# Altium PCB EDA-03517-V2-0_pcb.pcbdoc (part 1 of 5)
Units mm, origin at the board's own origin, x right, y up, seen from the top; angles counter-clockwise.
Board outline 220 x 264 mm, 8 copper layers (Top Layer, L2, L3, L4, L5, L6, L7, Bottom Layer), stack 2.18 mm thick; 439 components, 290 nets, 1011 pads, 273 vias.
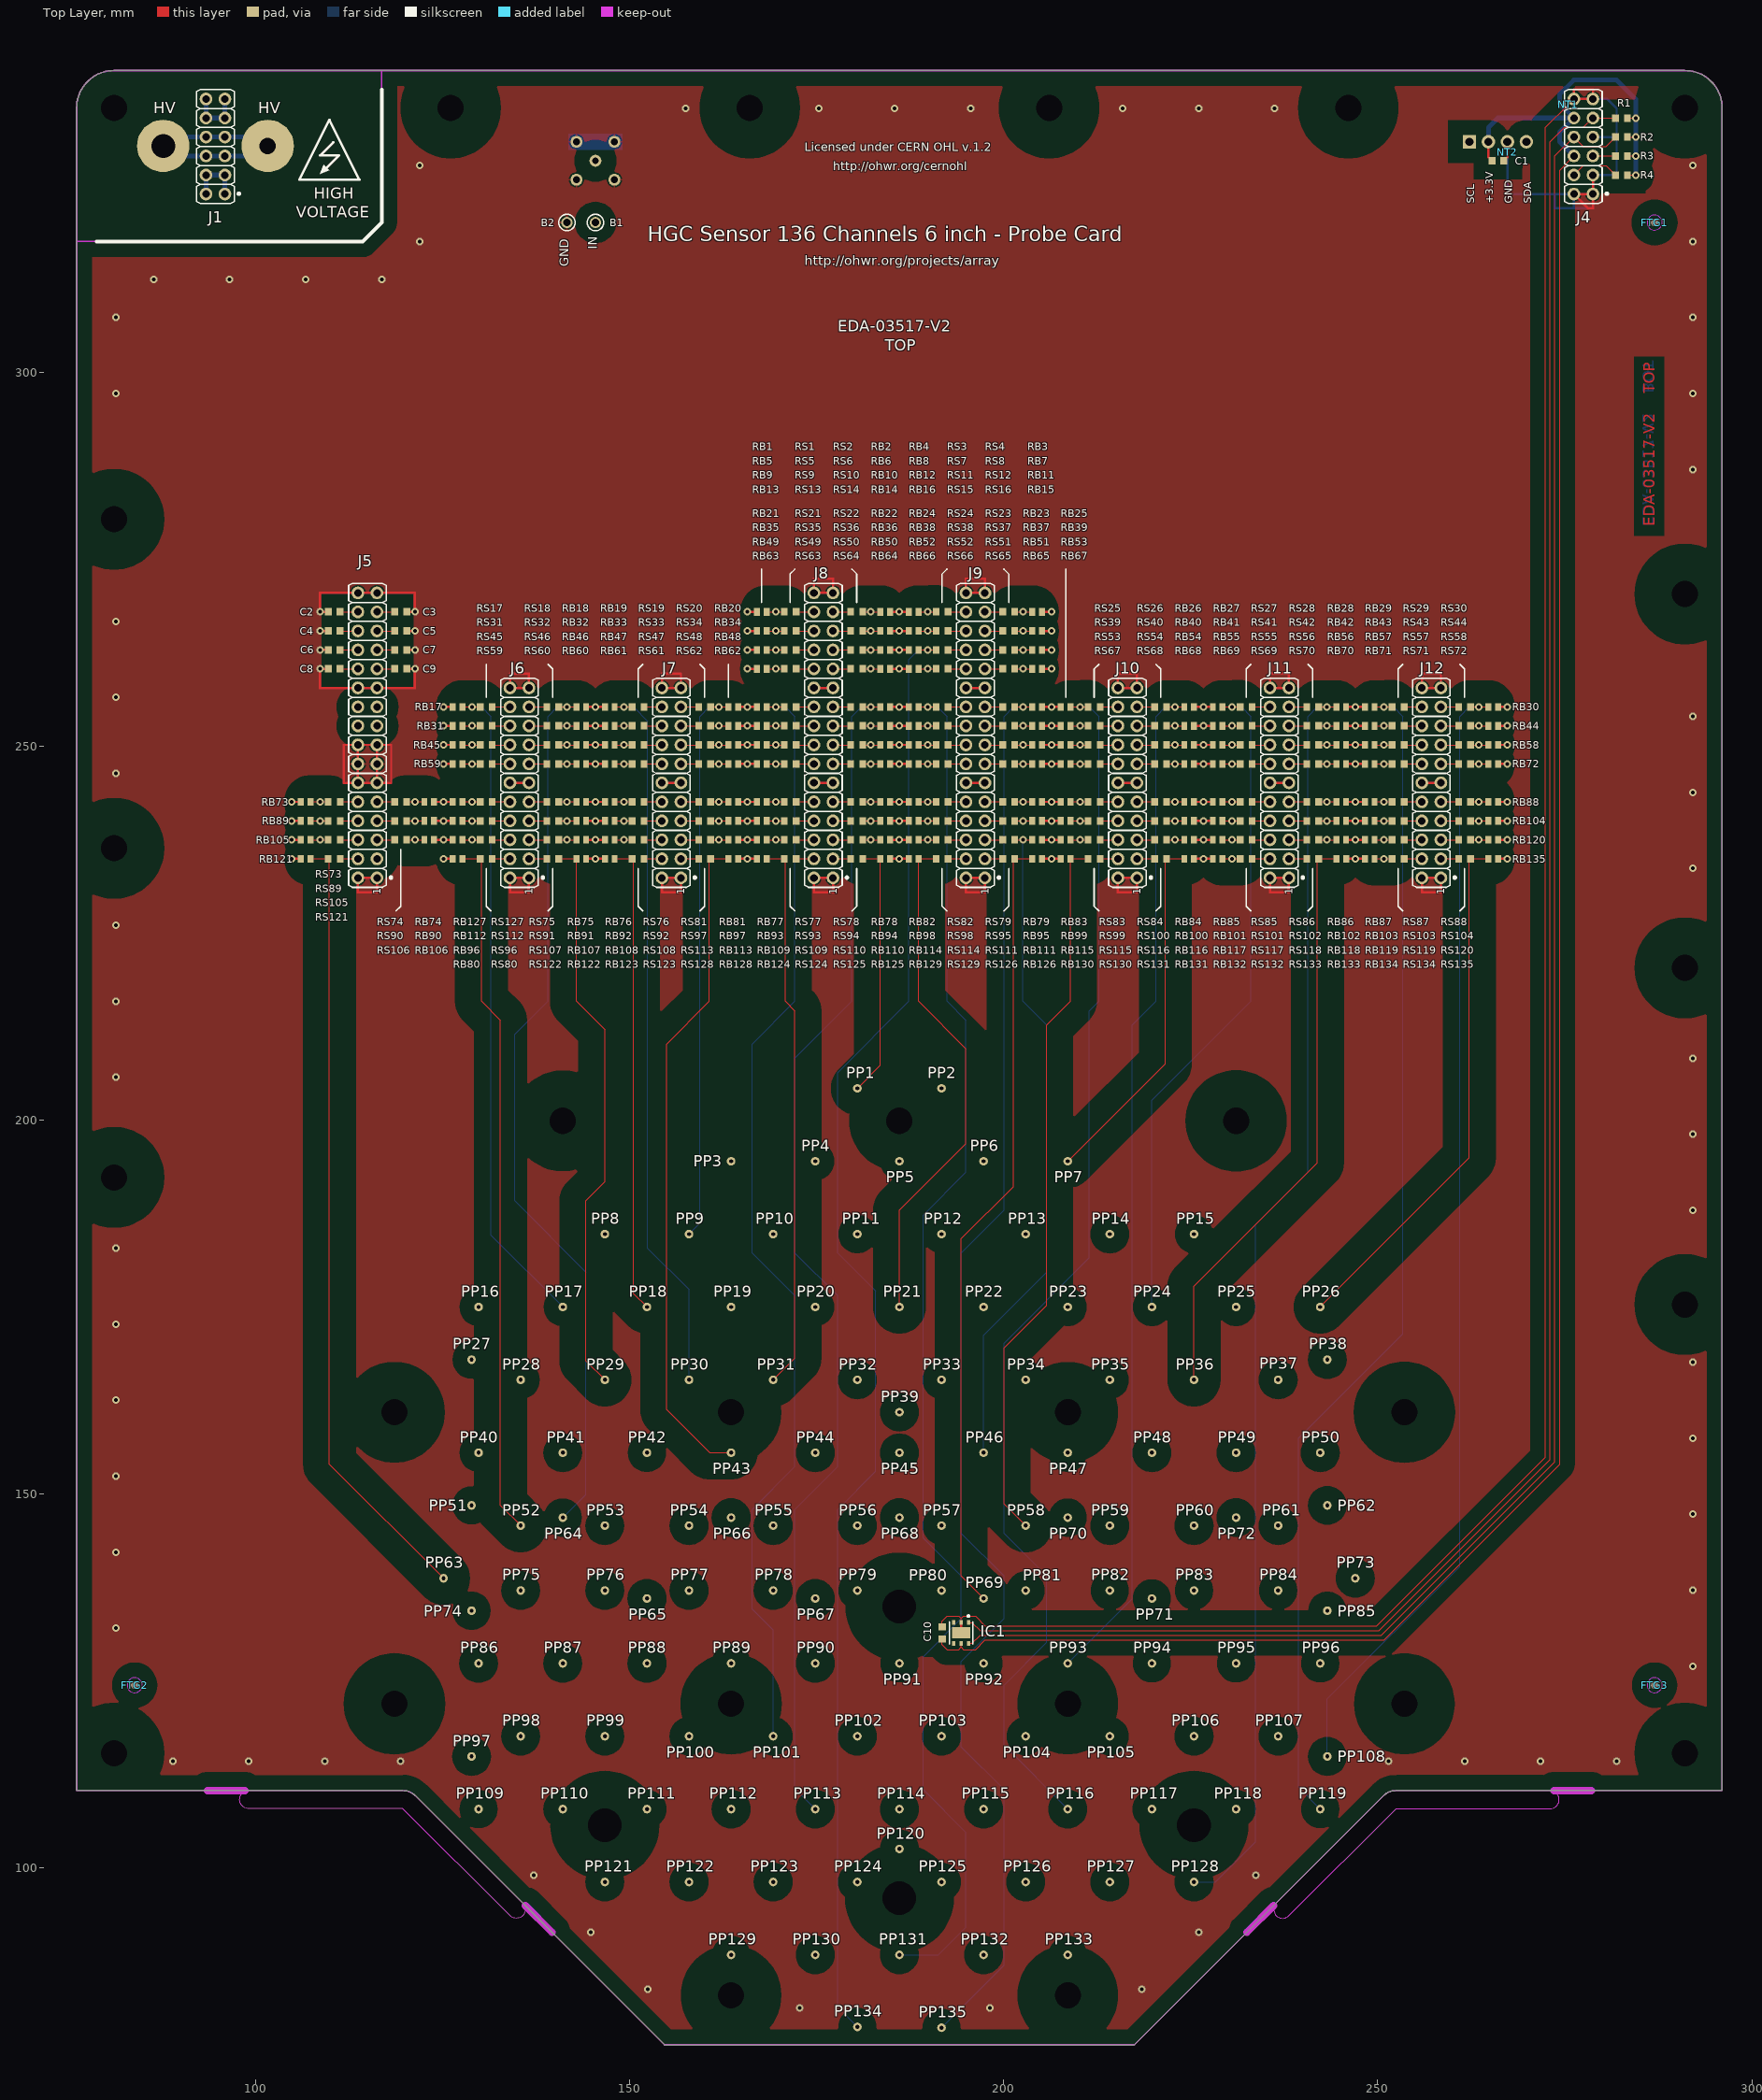
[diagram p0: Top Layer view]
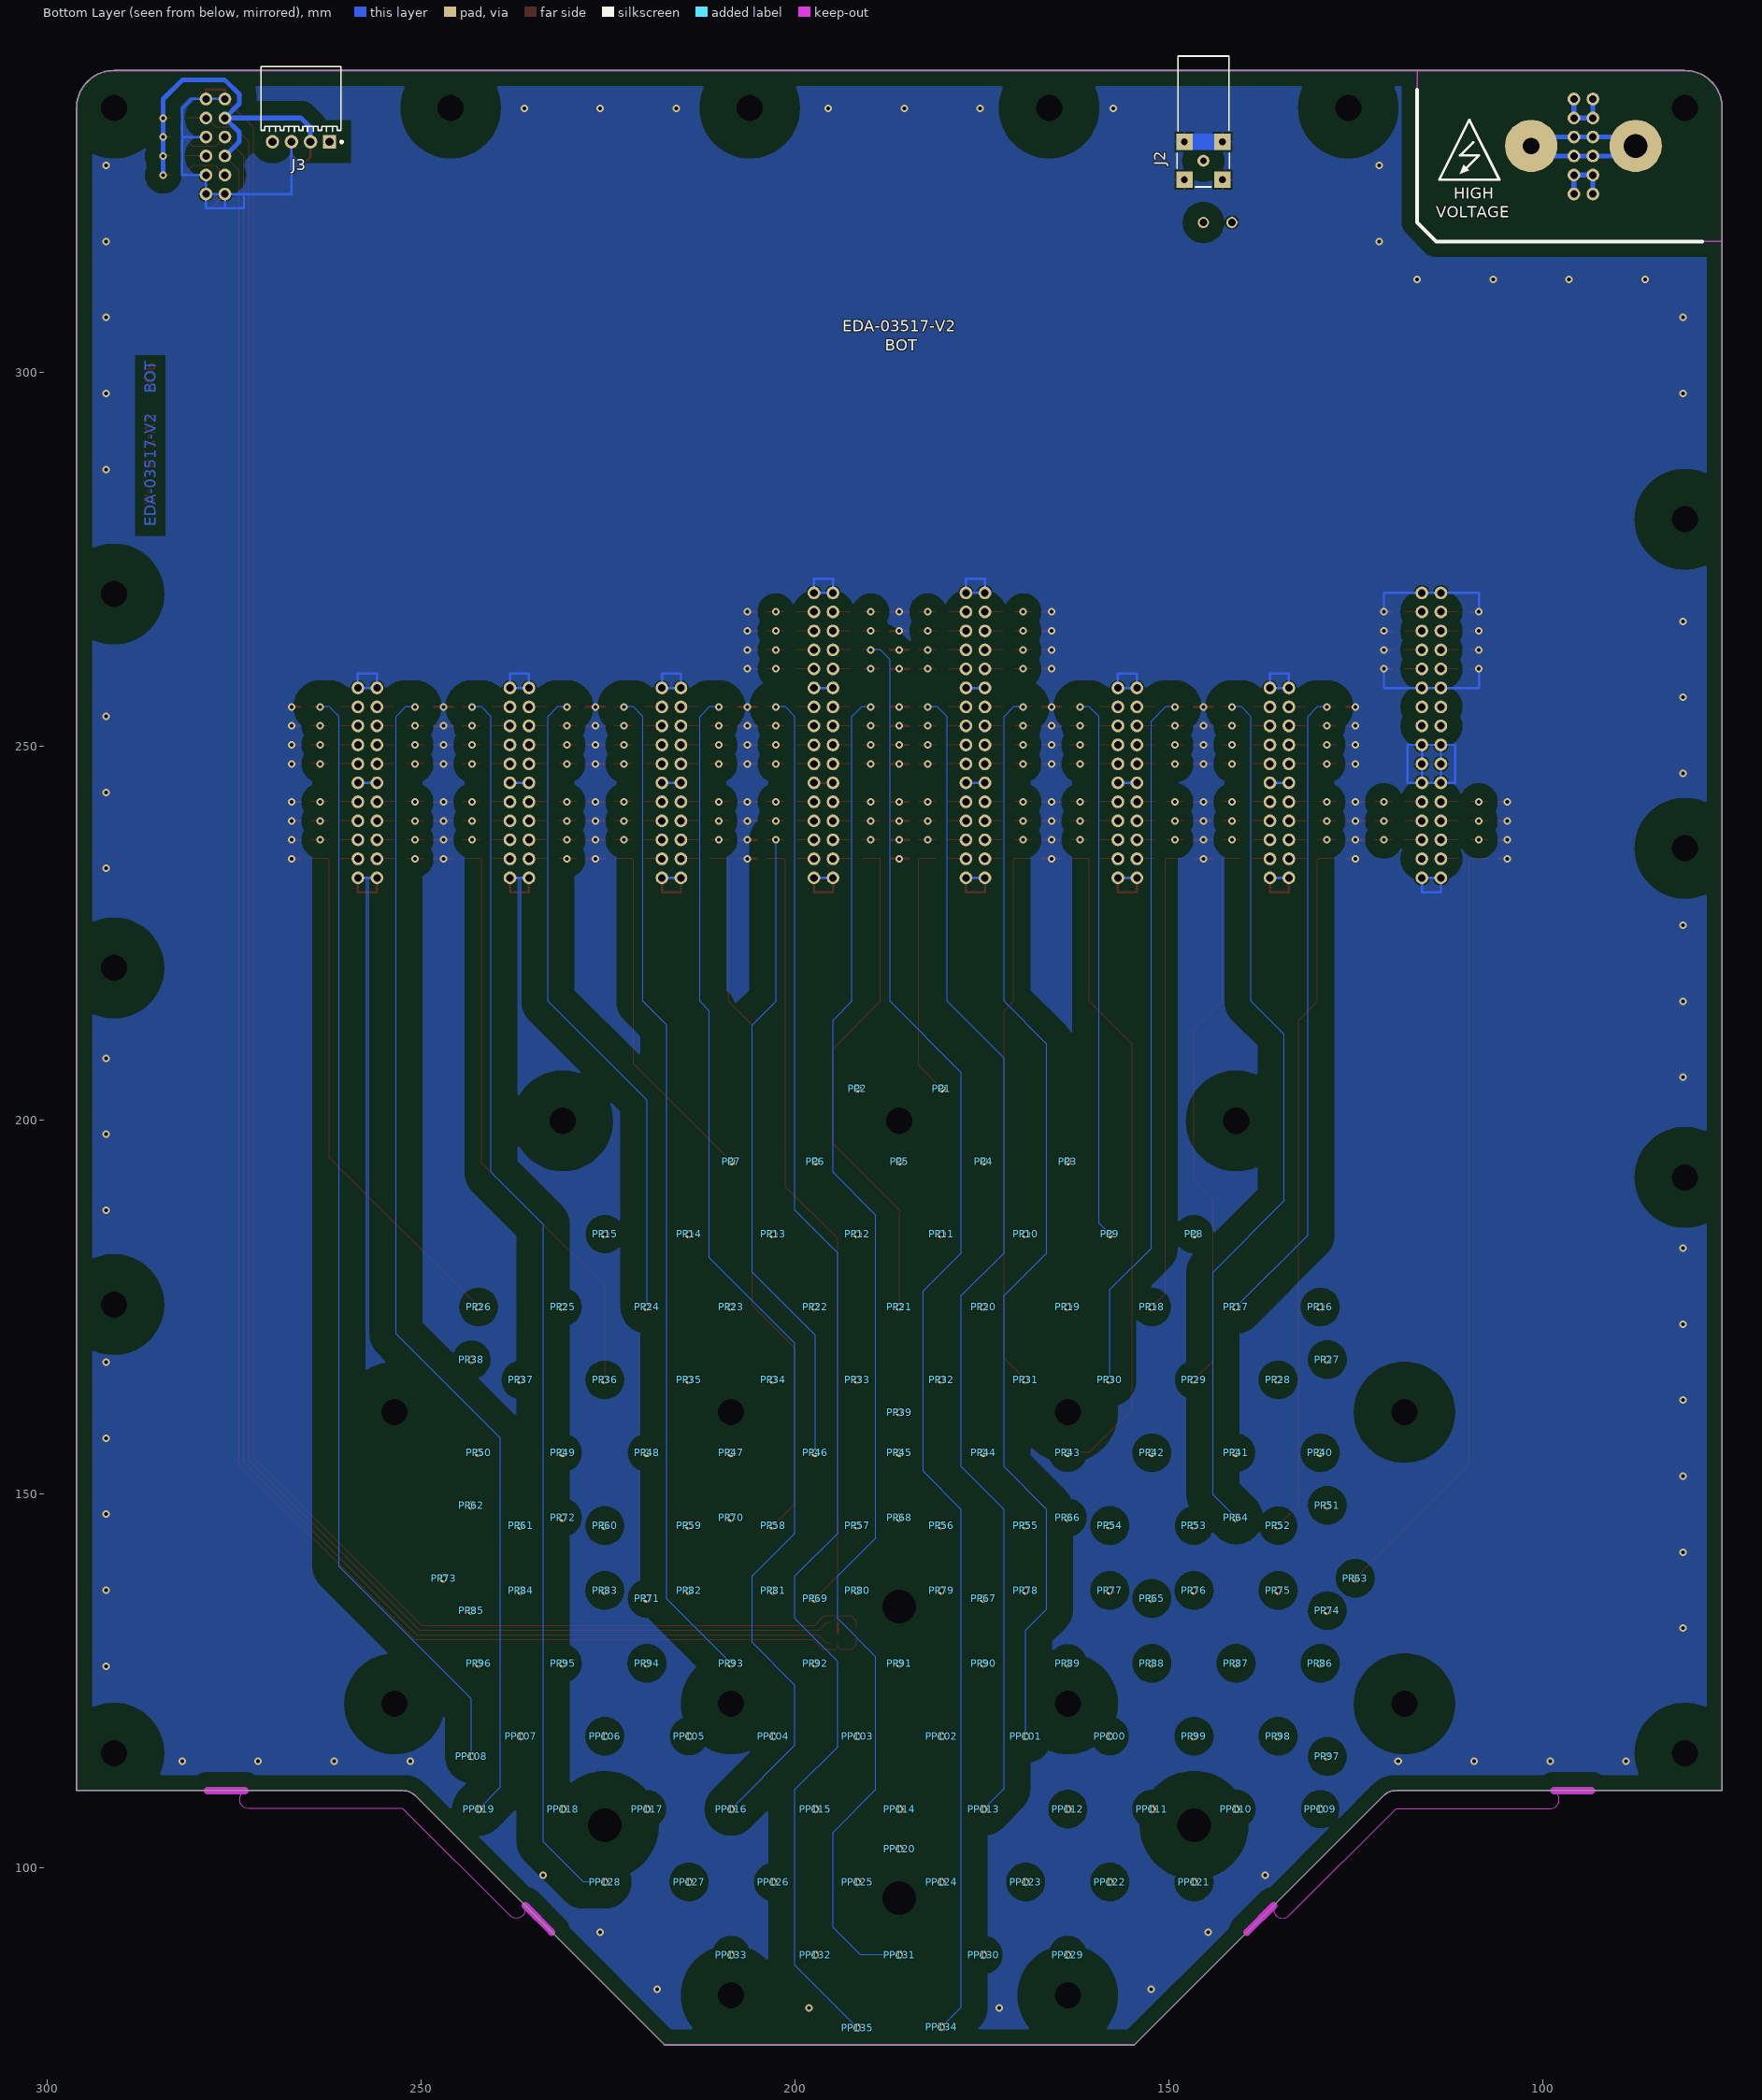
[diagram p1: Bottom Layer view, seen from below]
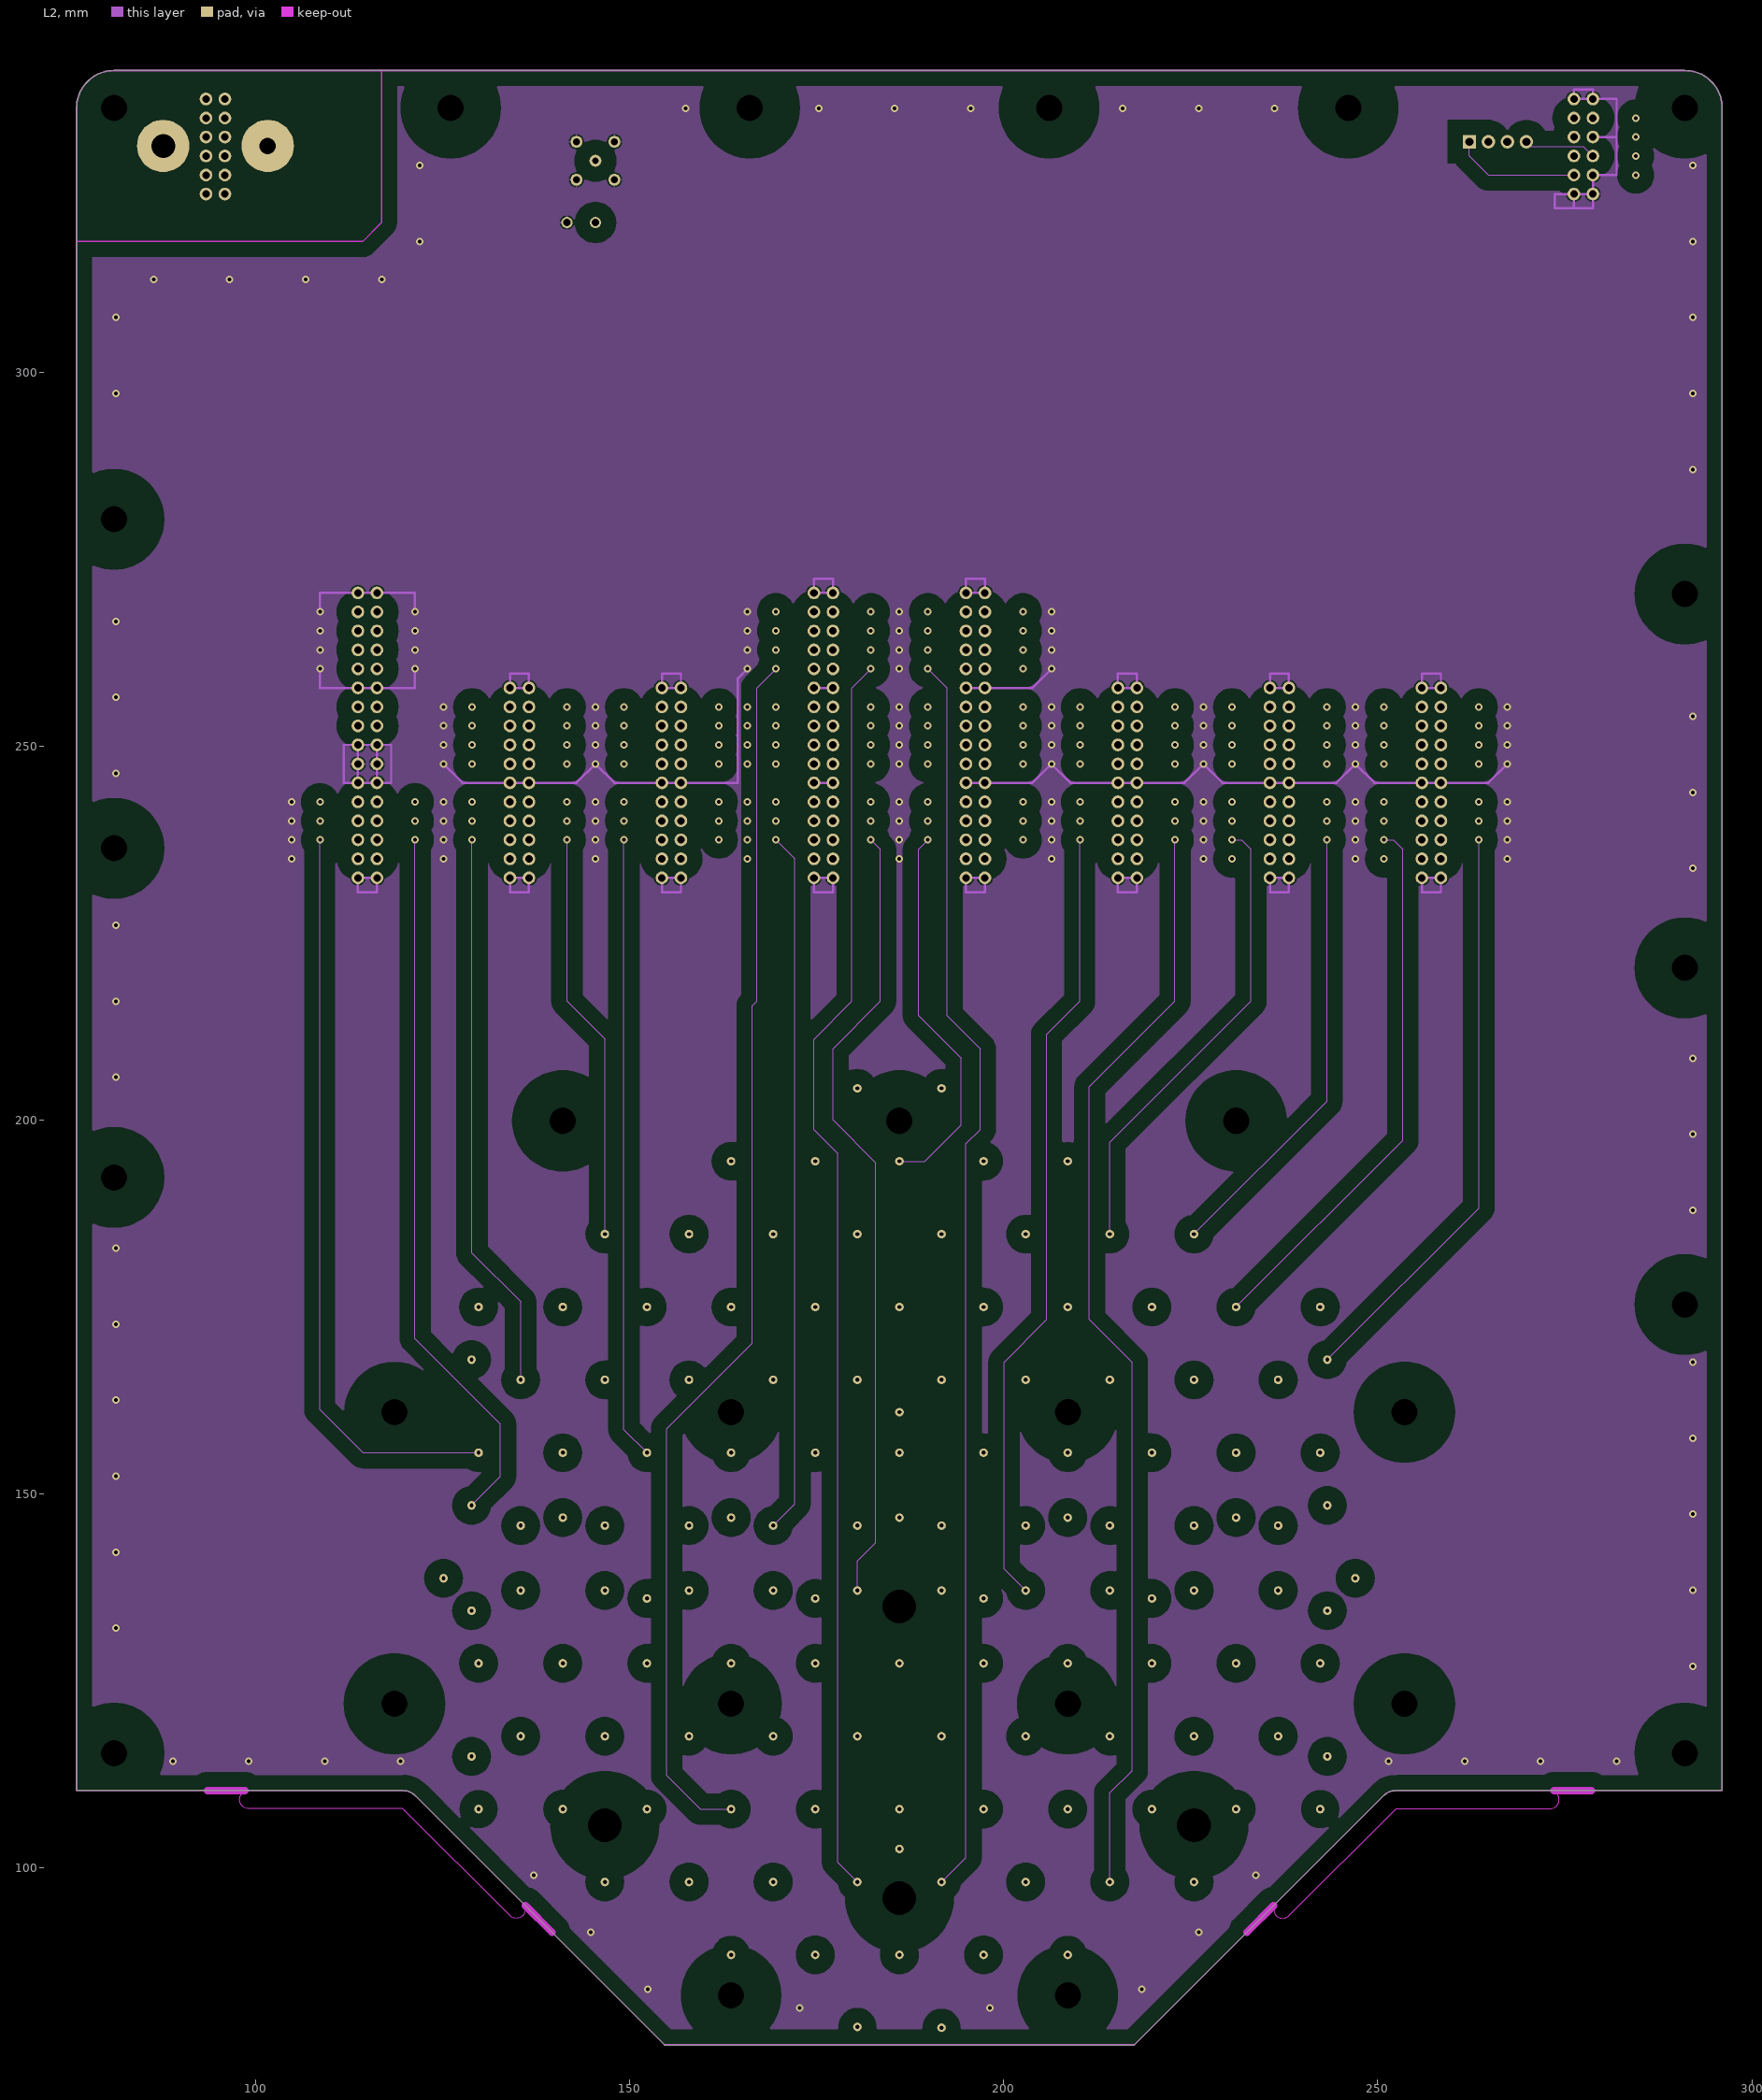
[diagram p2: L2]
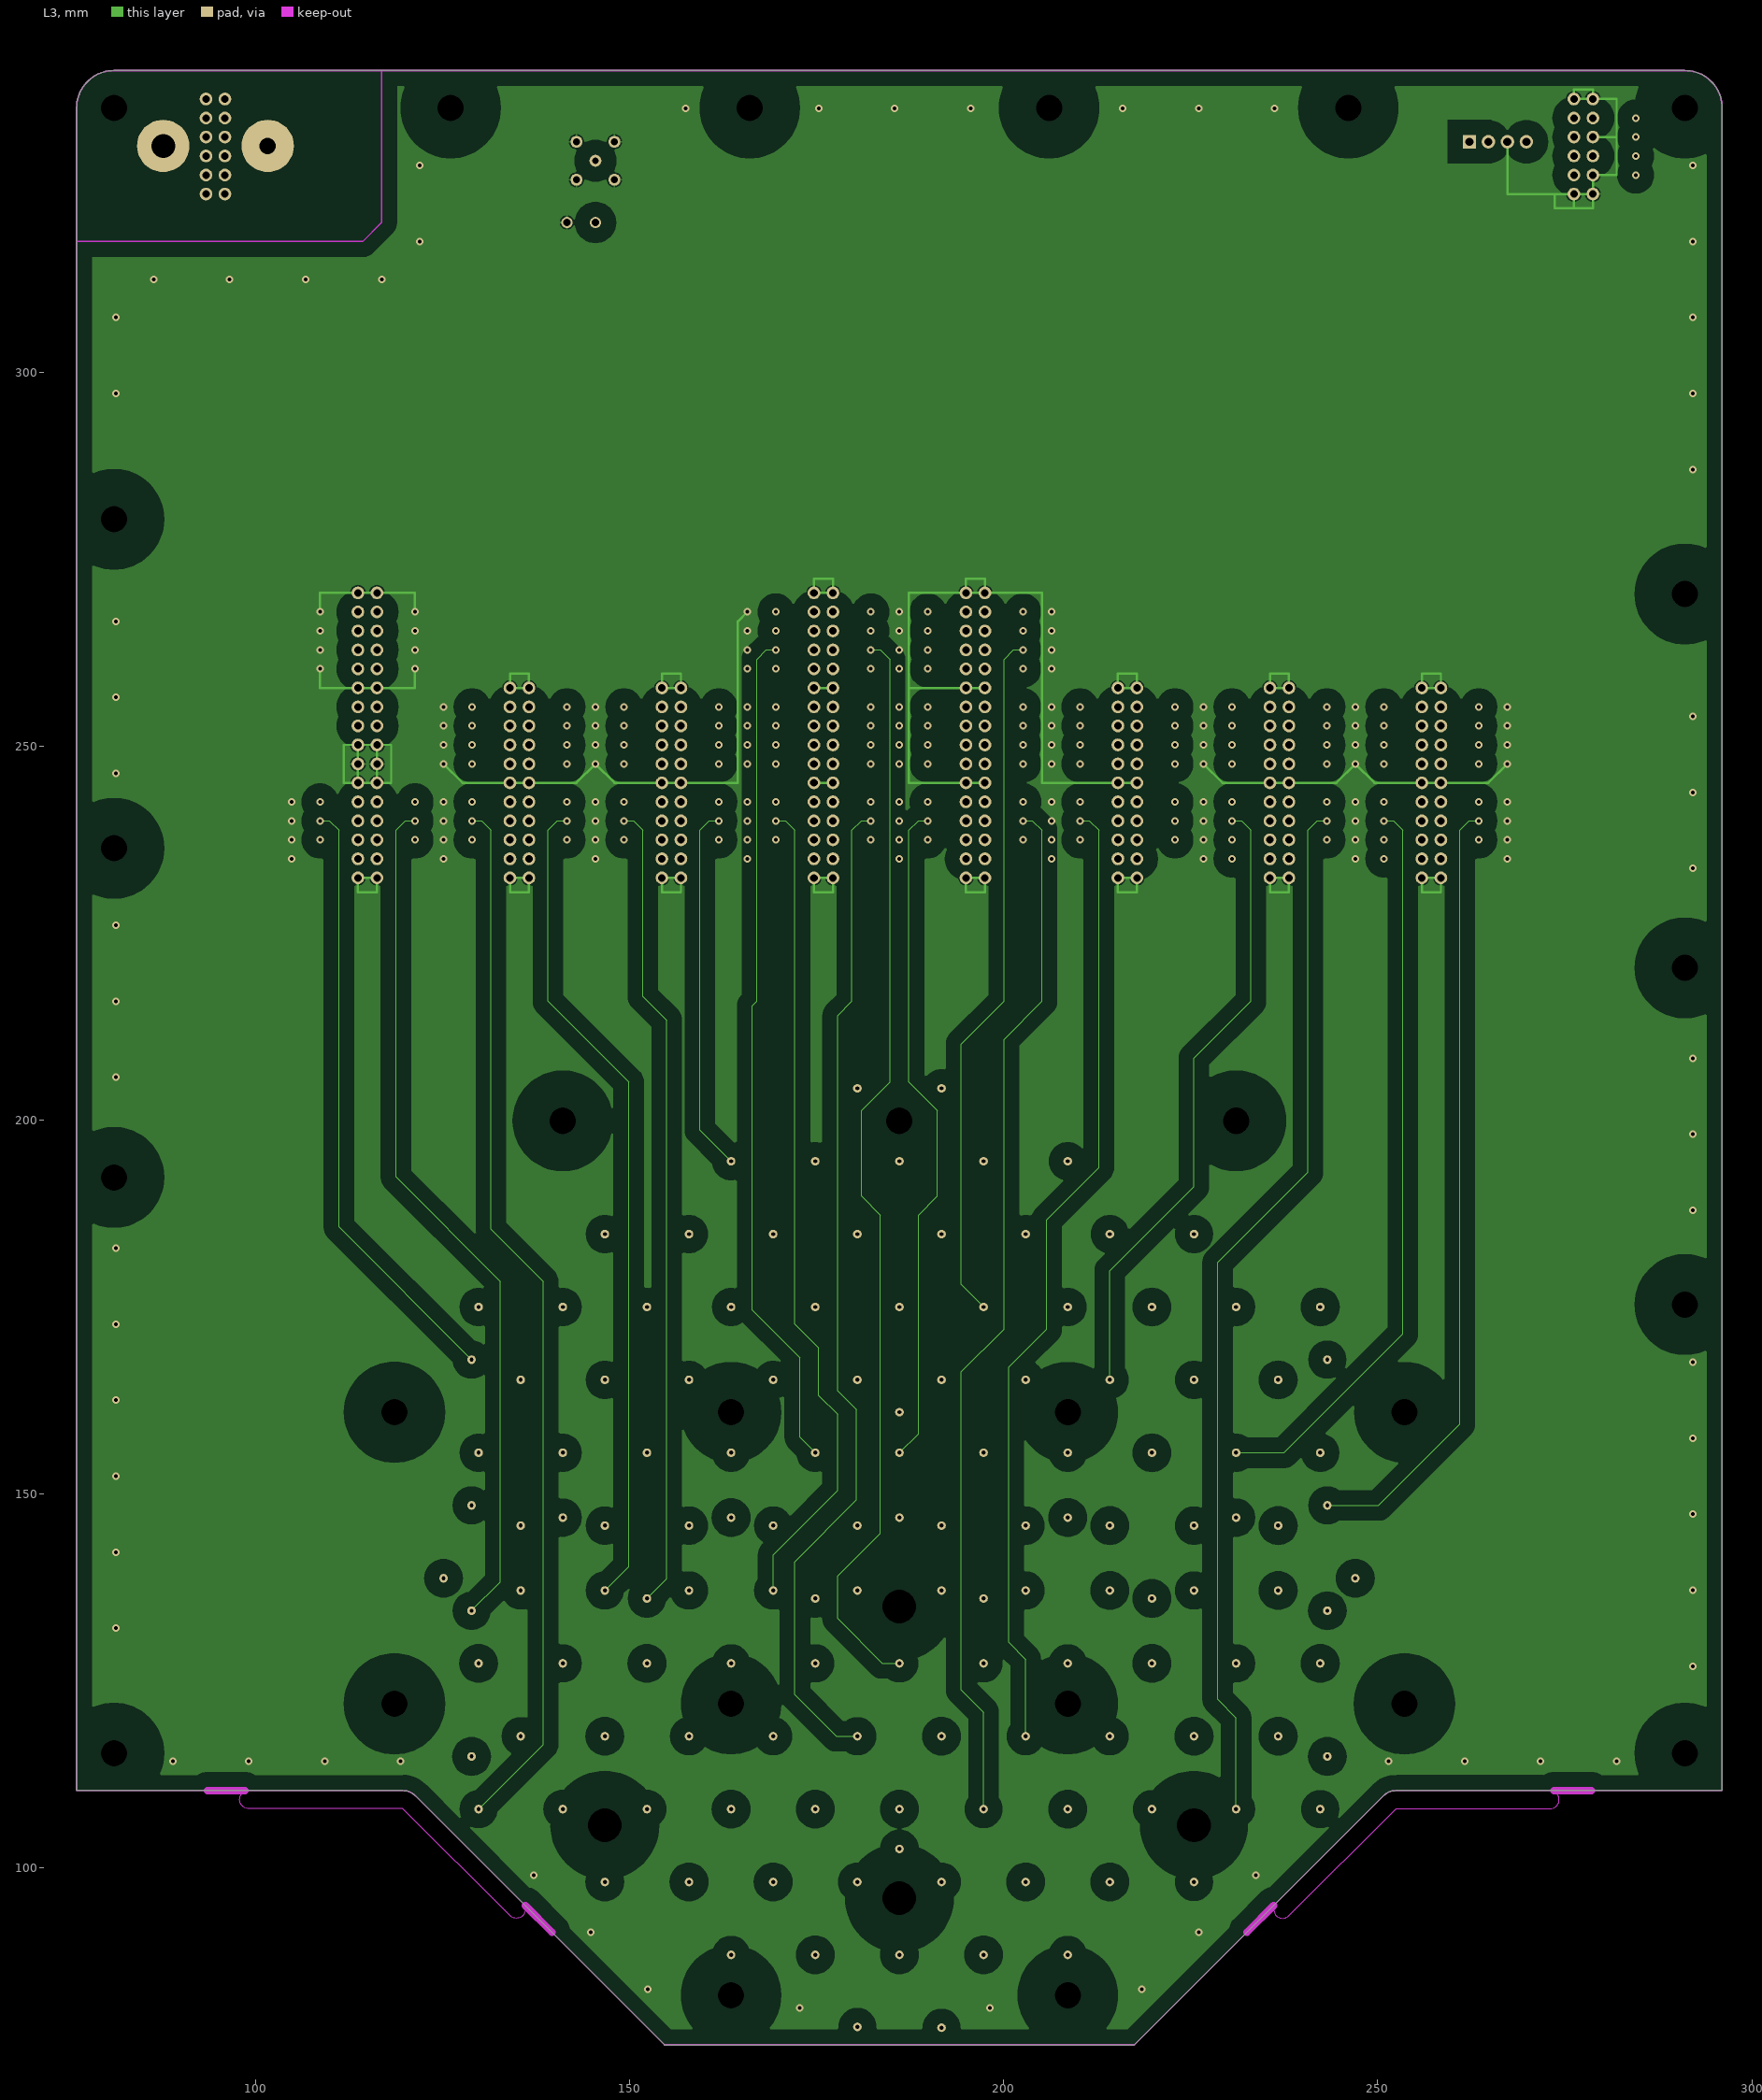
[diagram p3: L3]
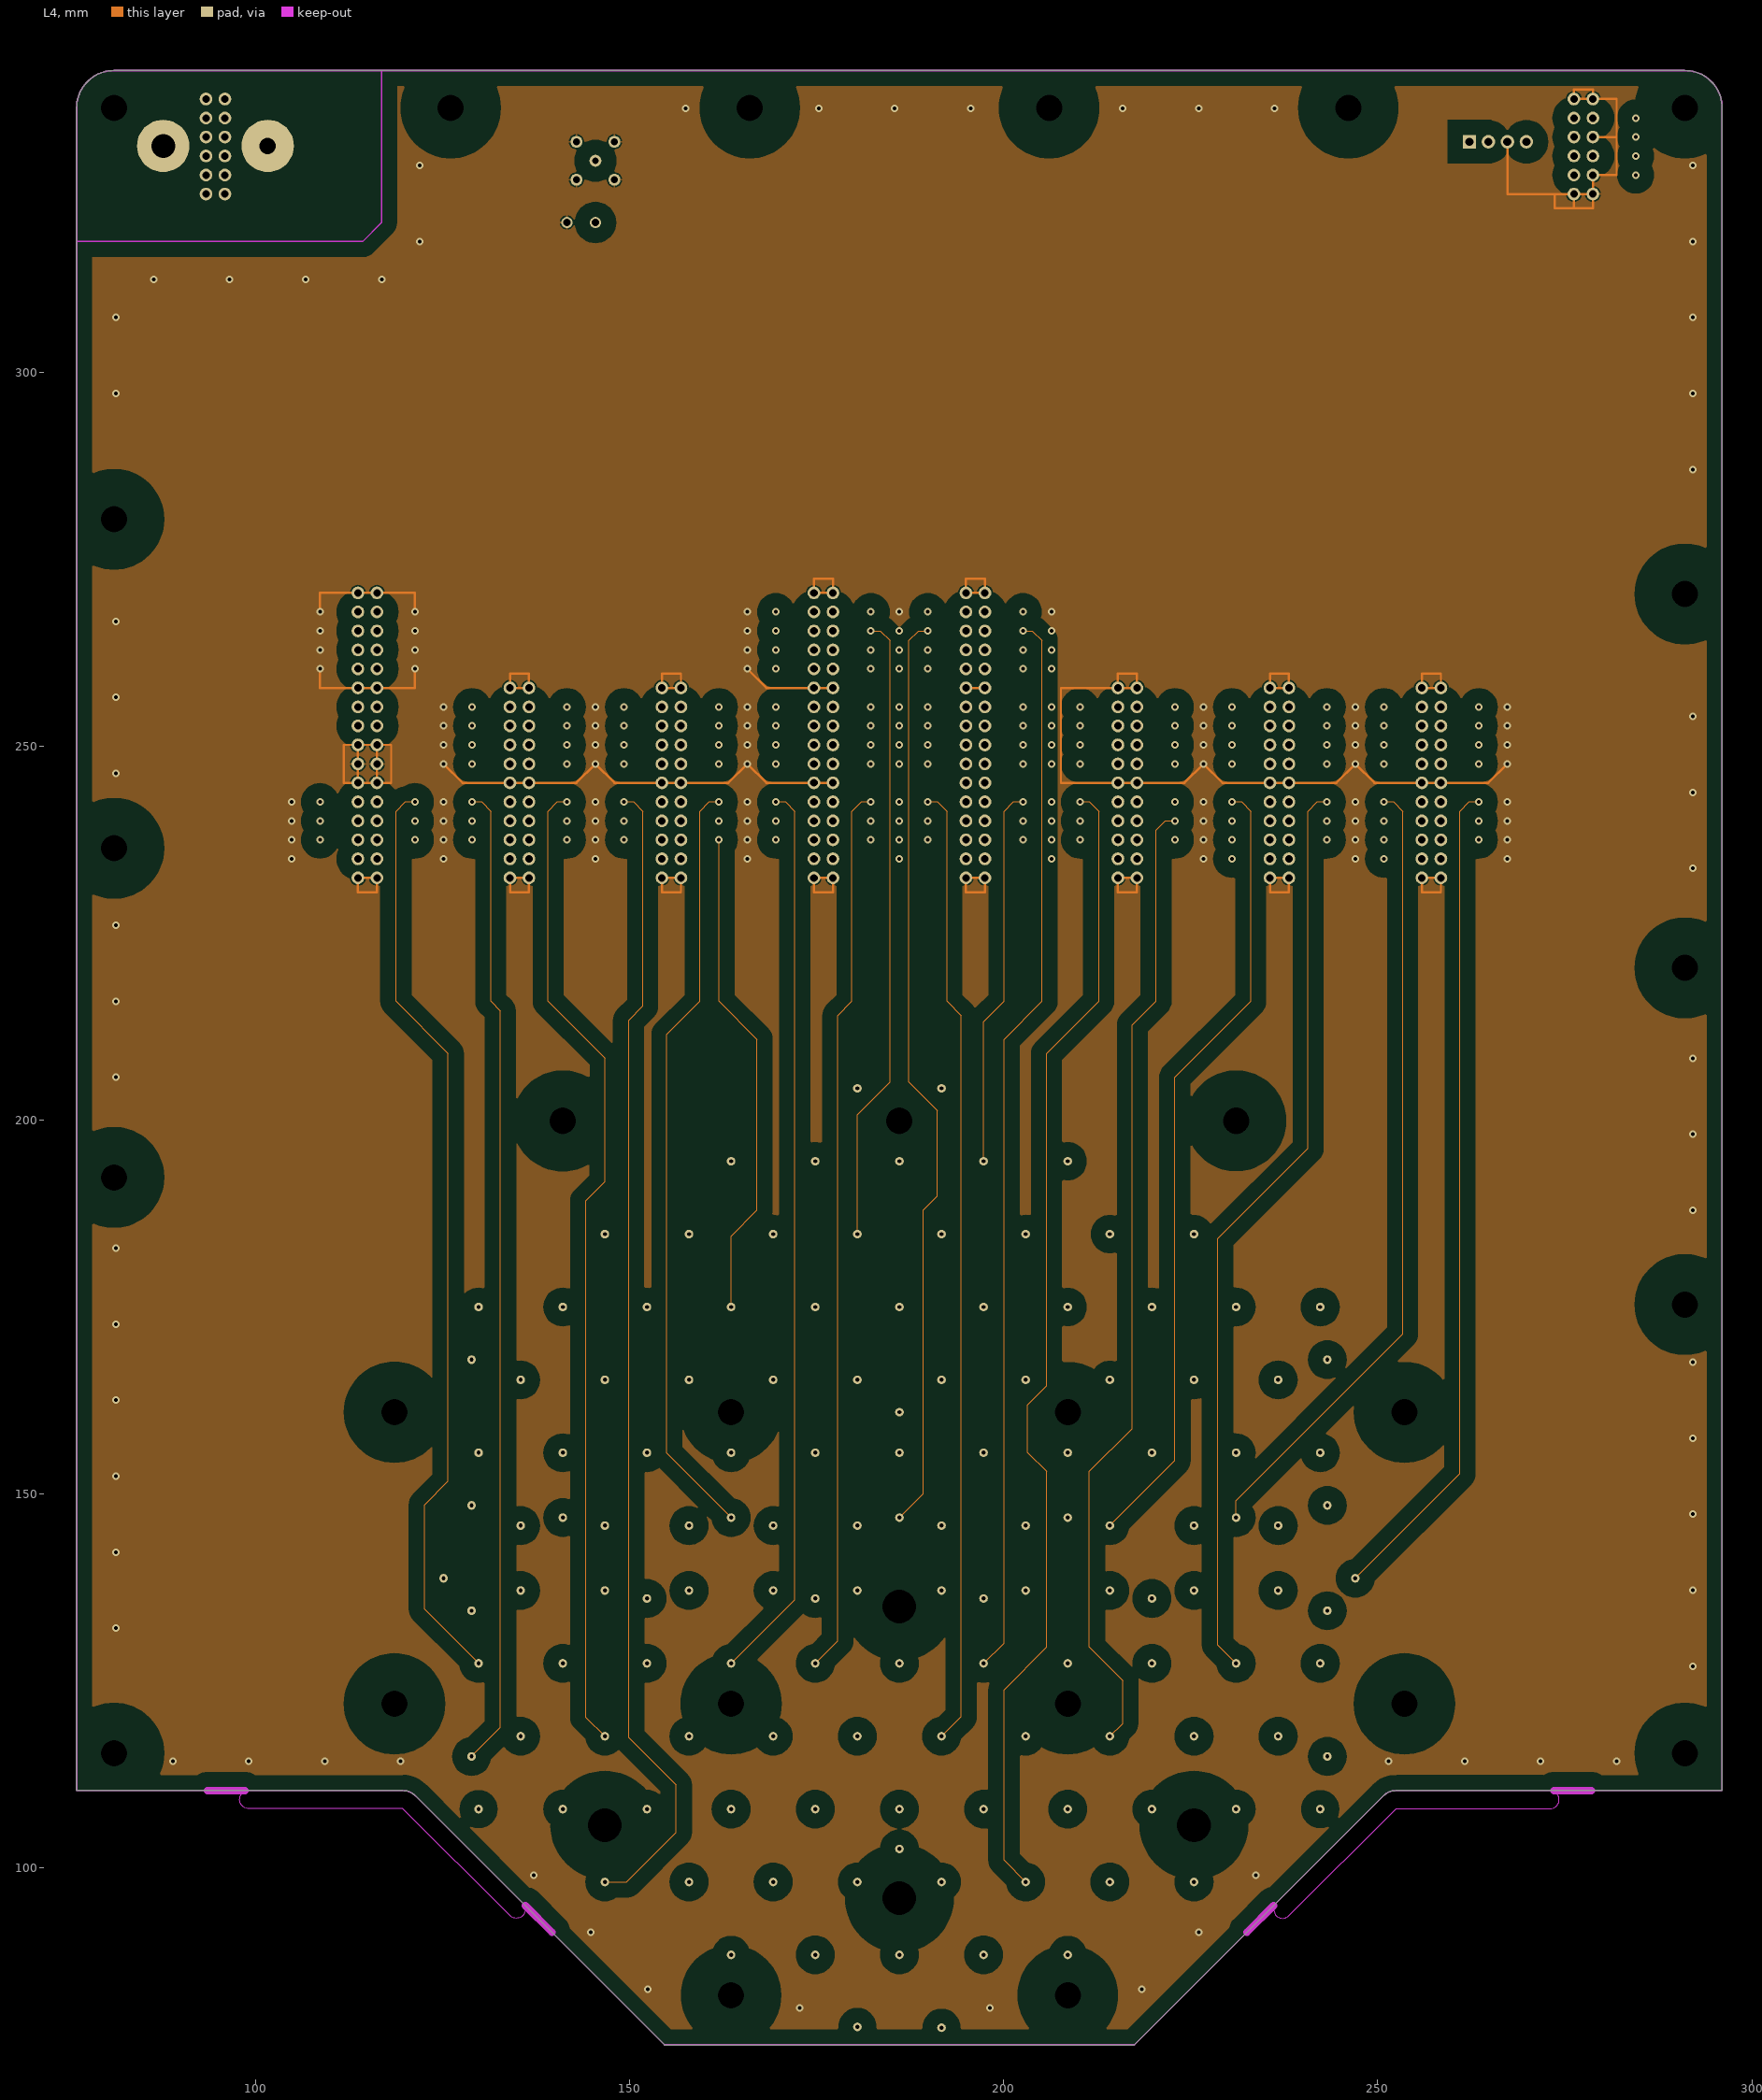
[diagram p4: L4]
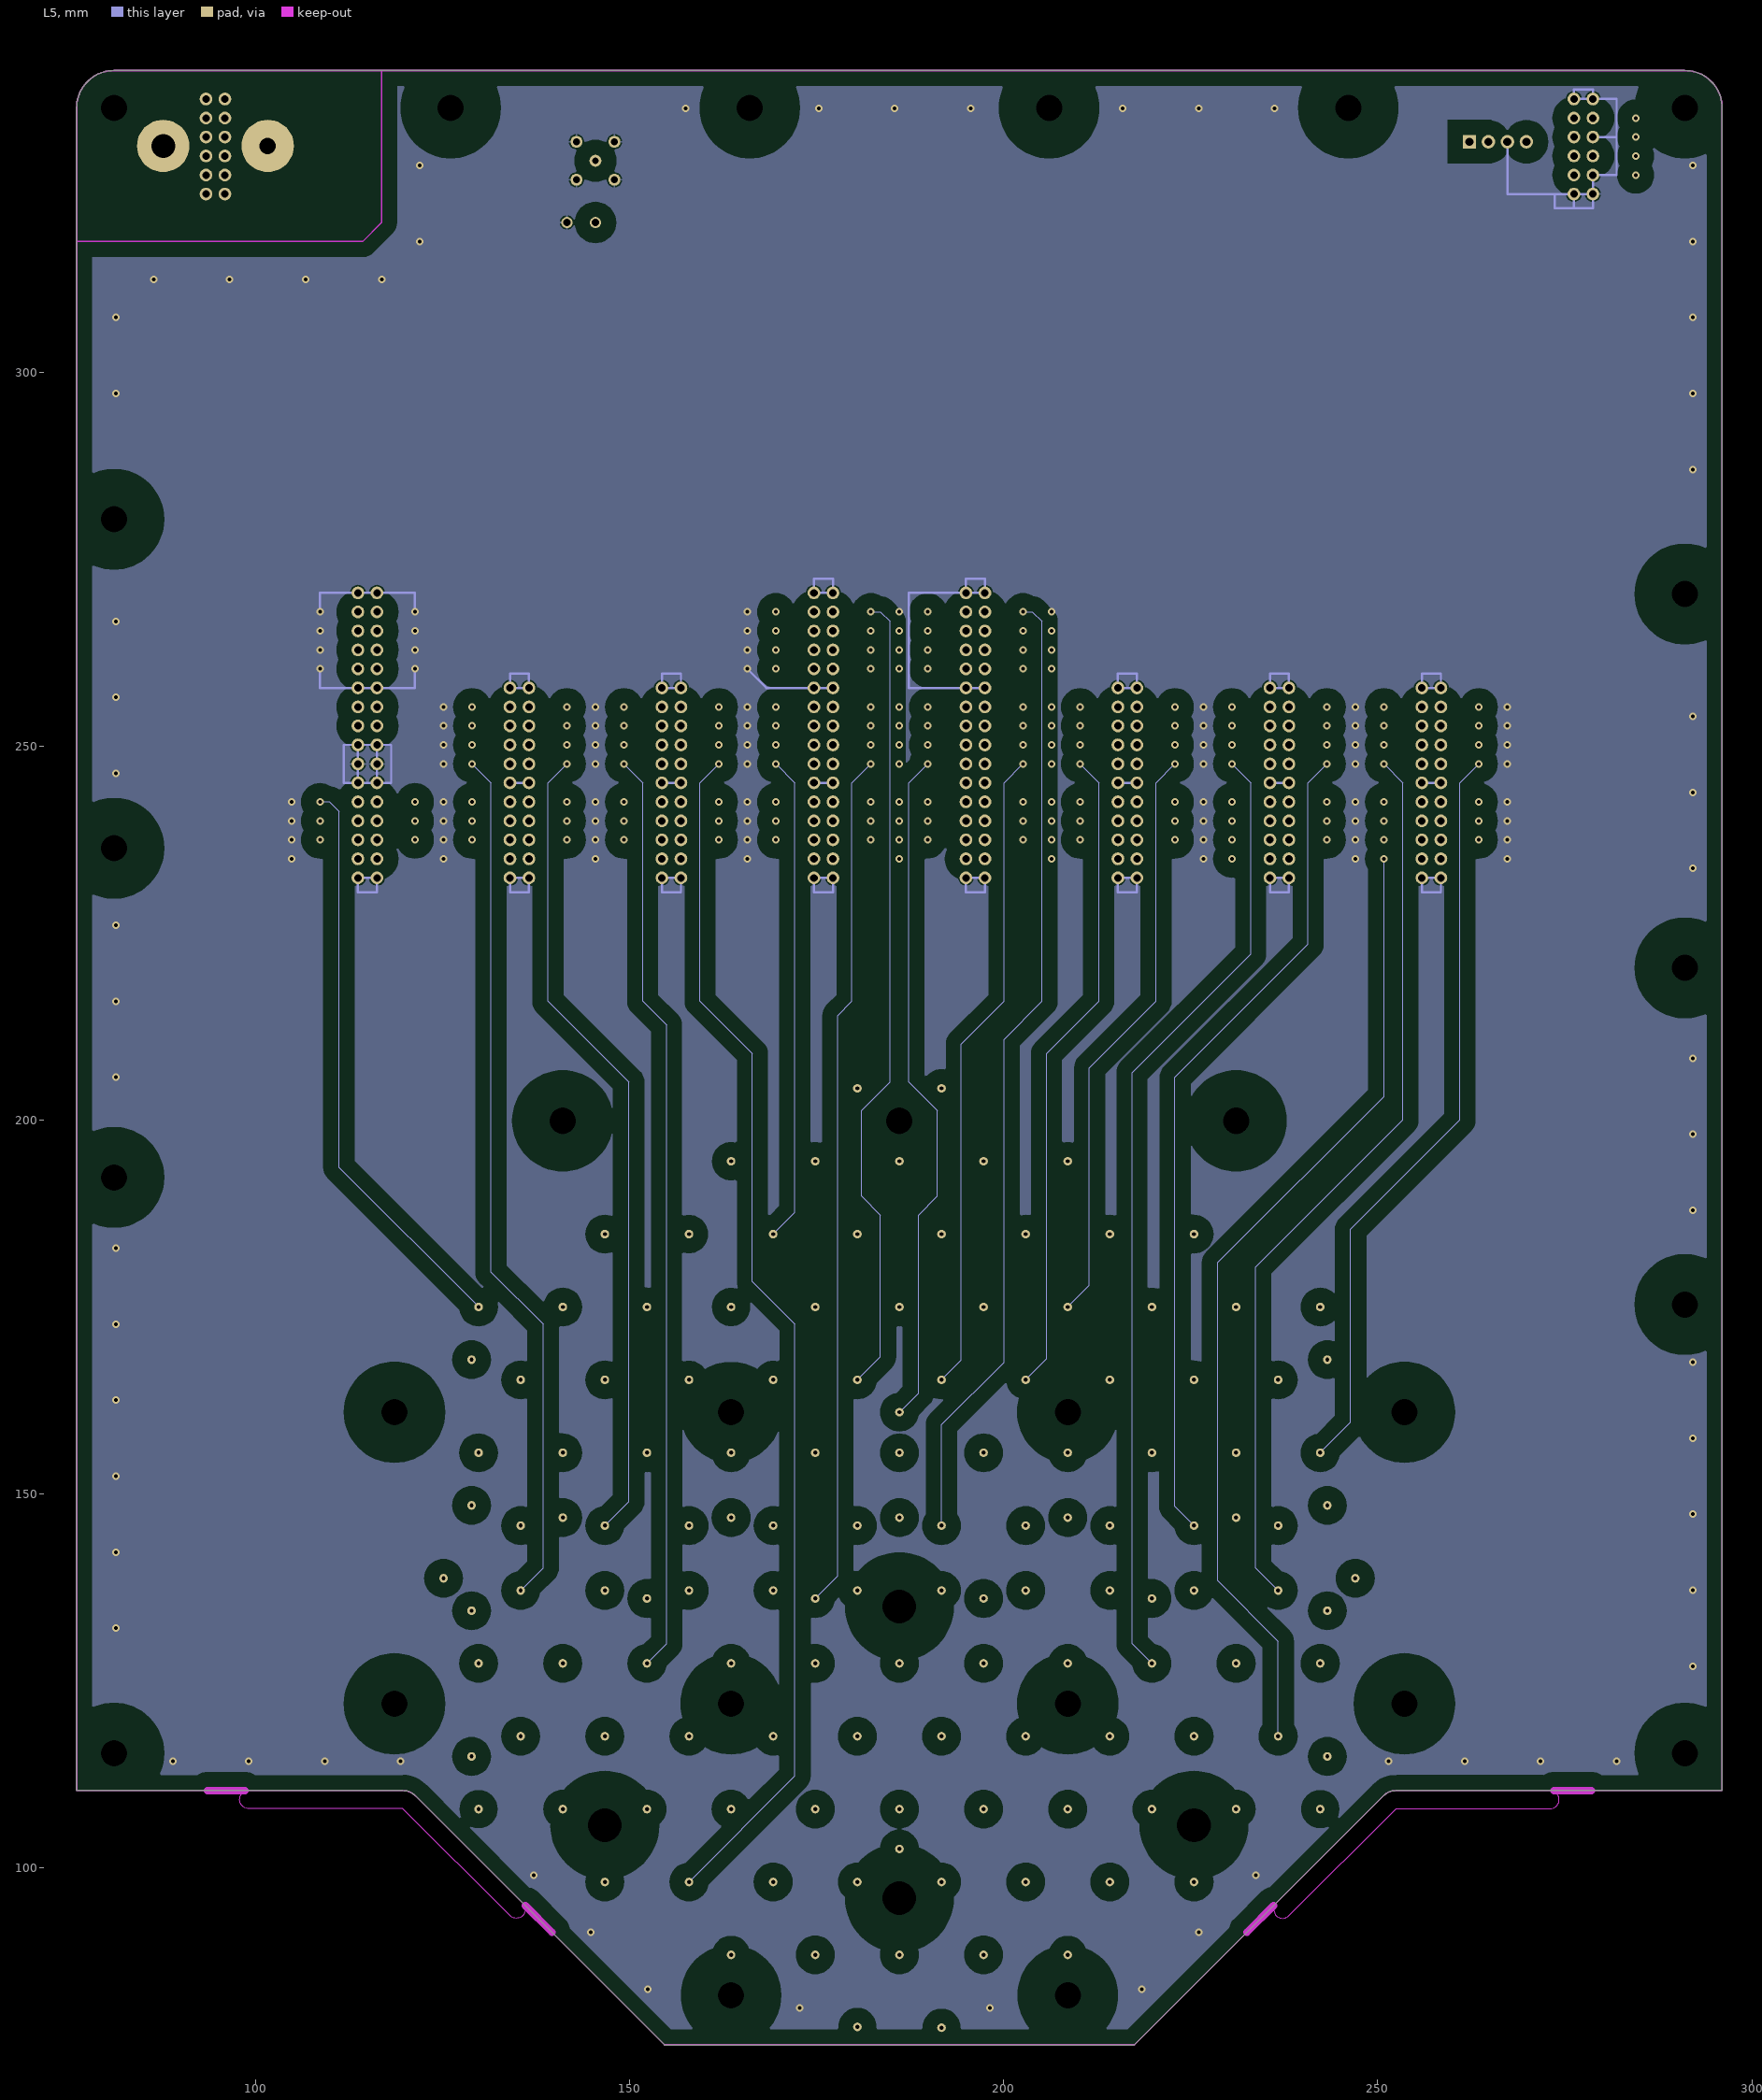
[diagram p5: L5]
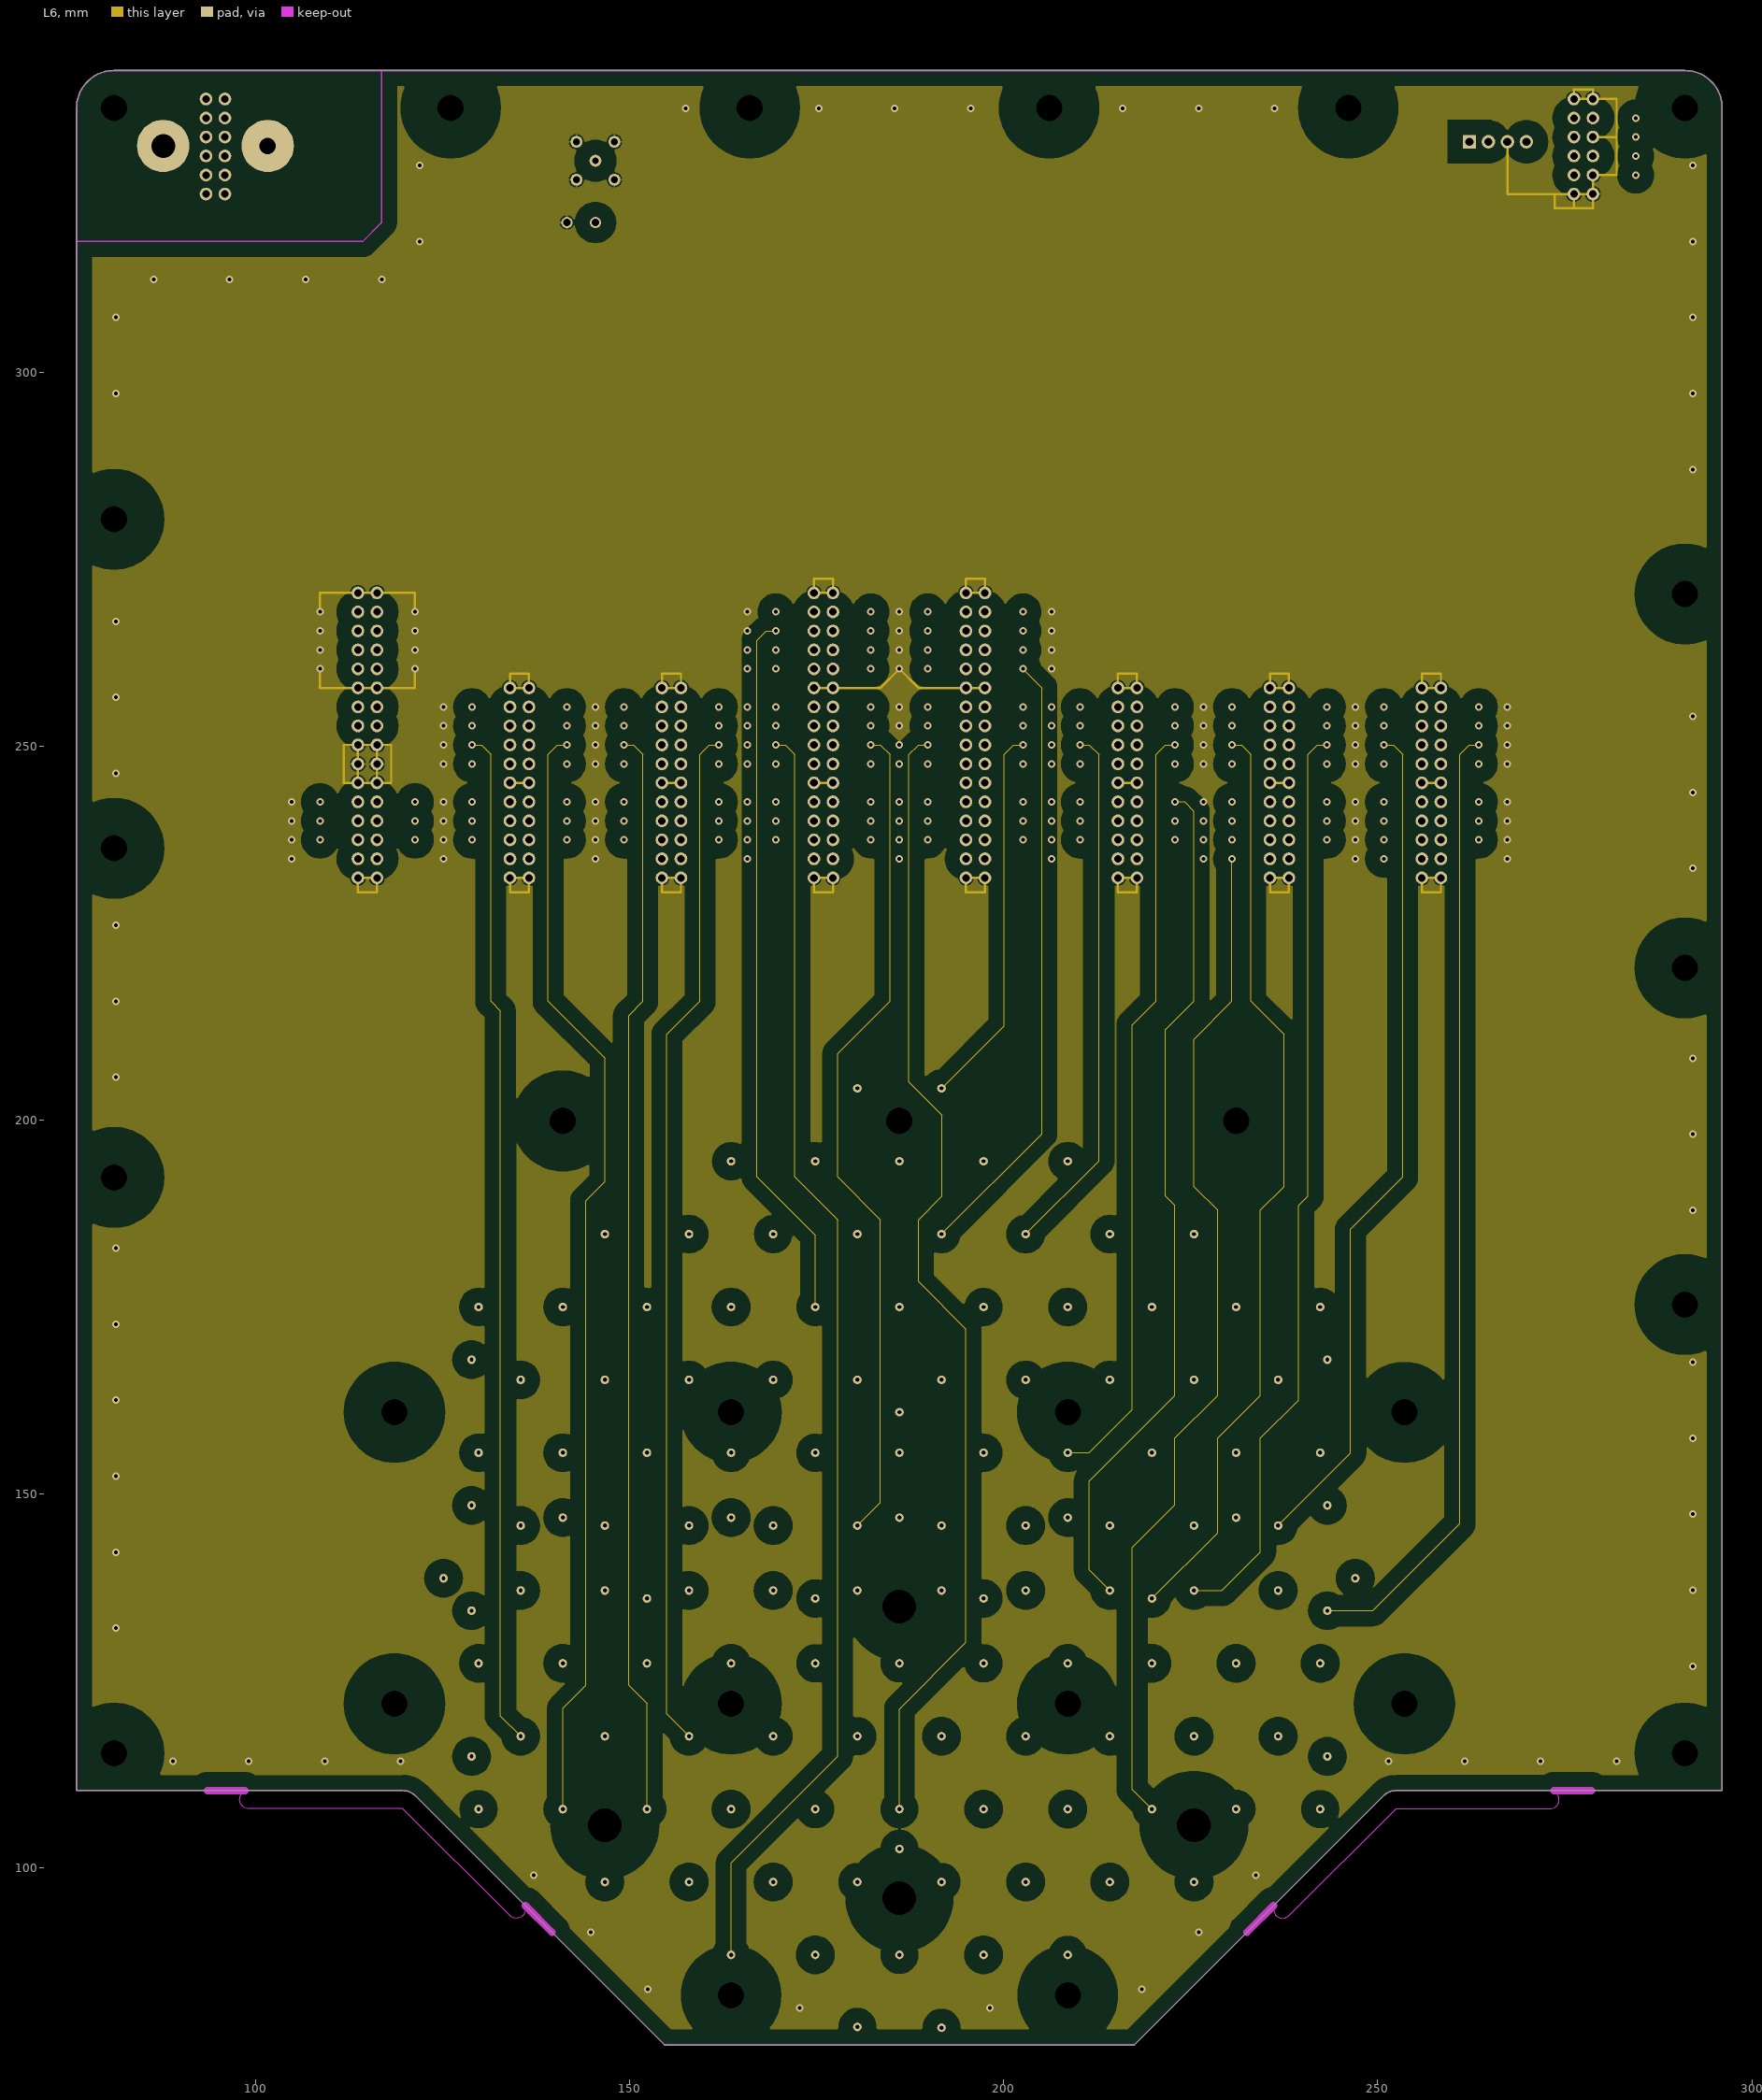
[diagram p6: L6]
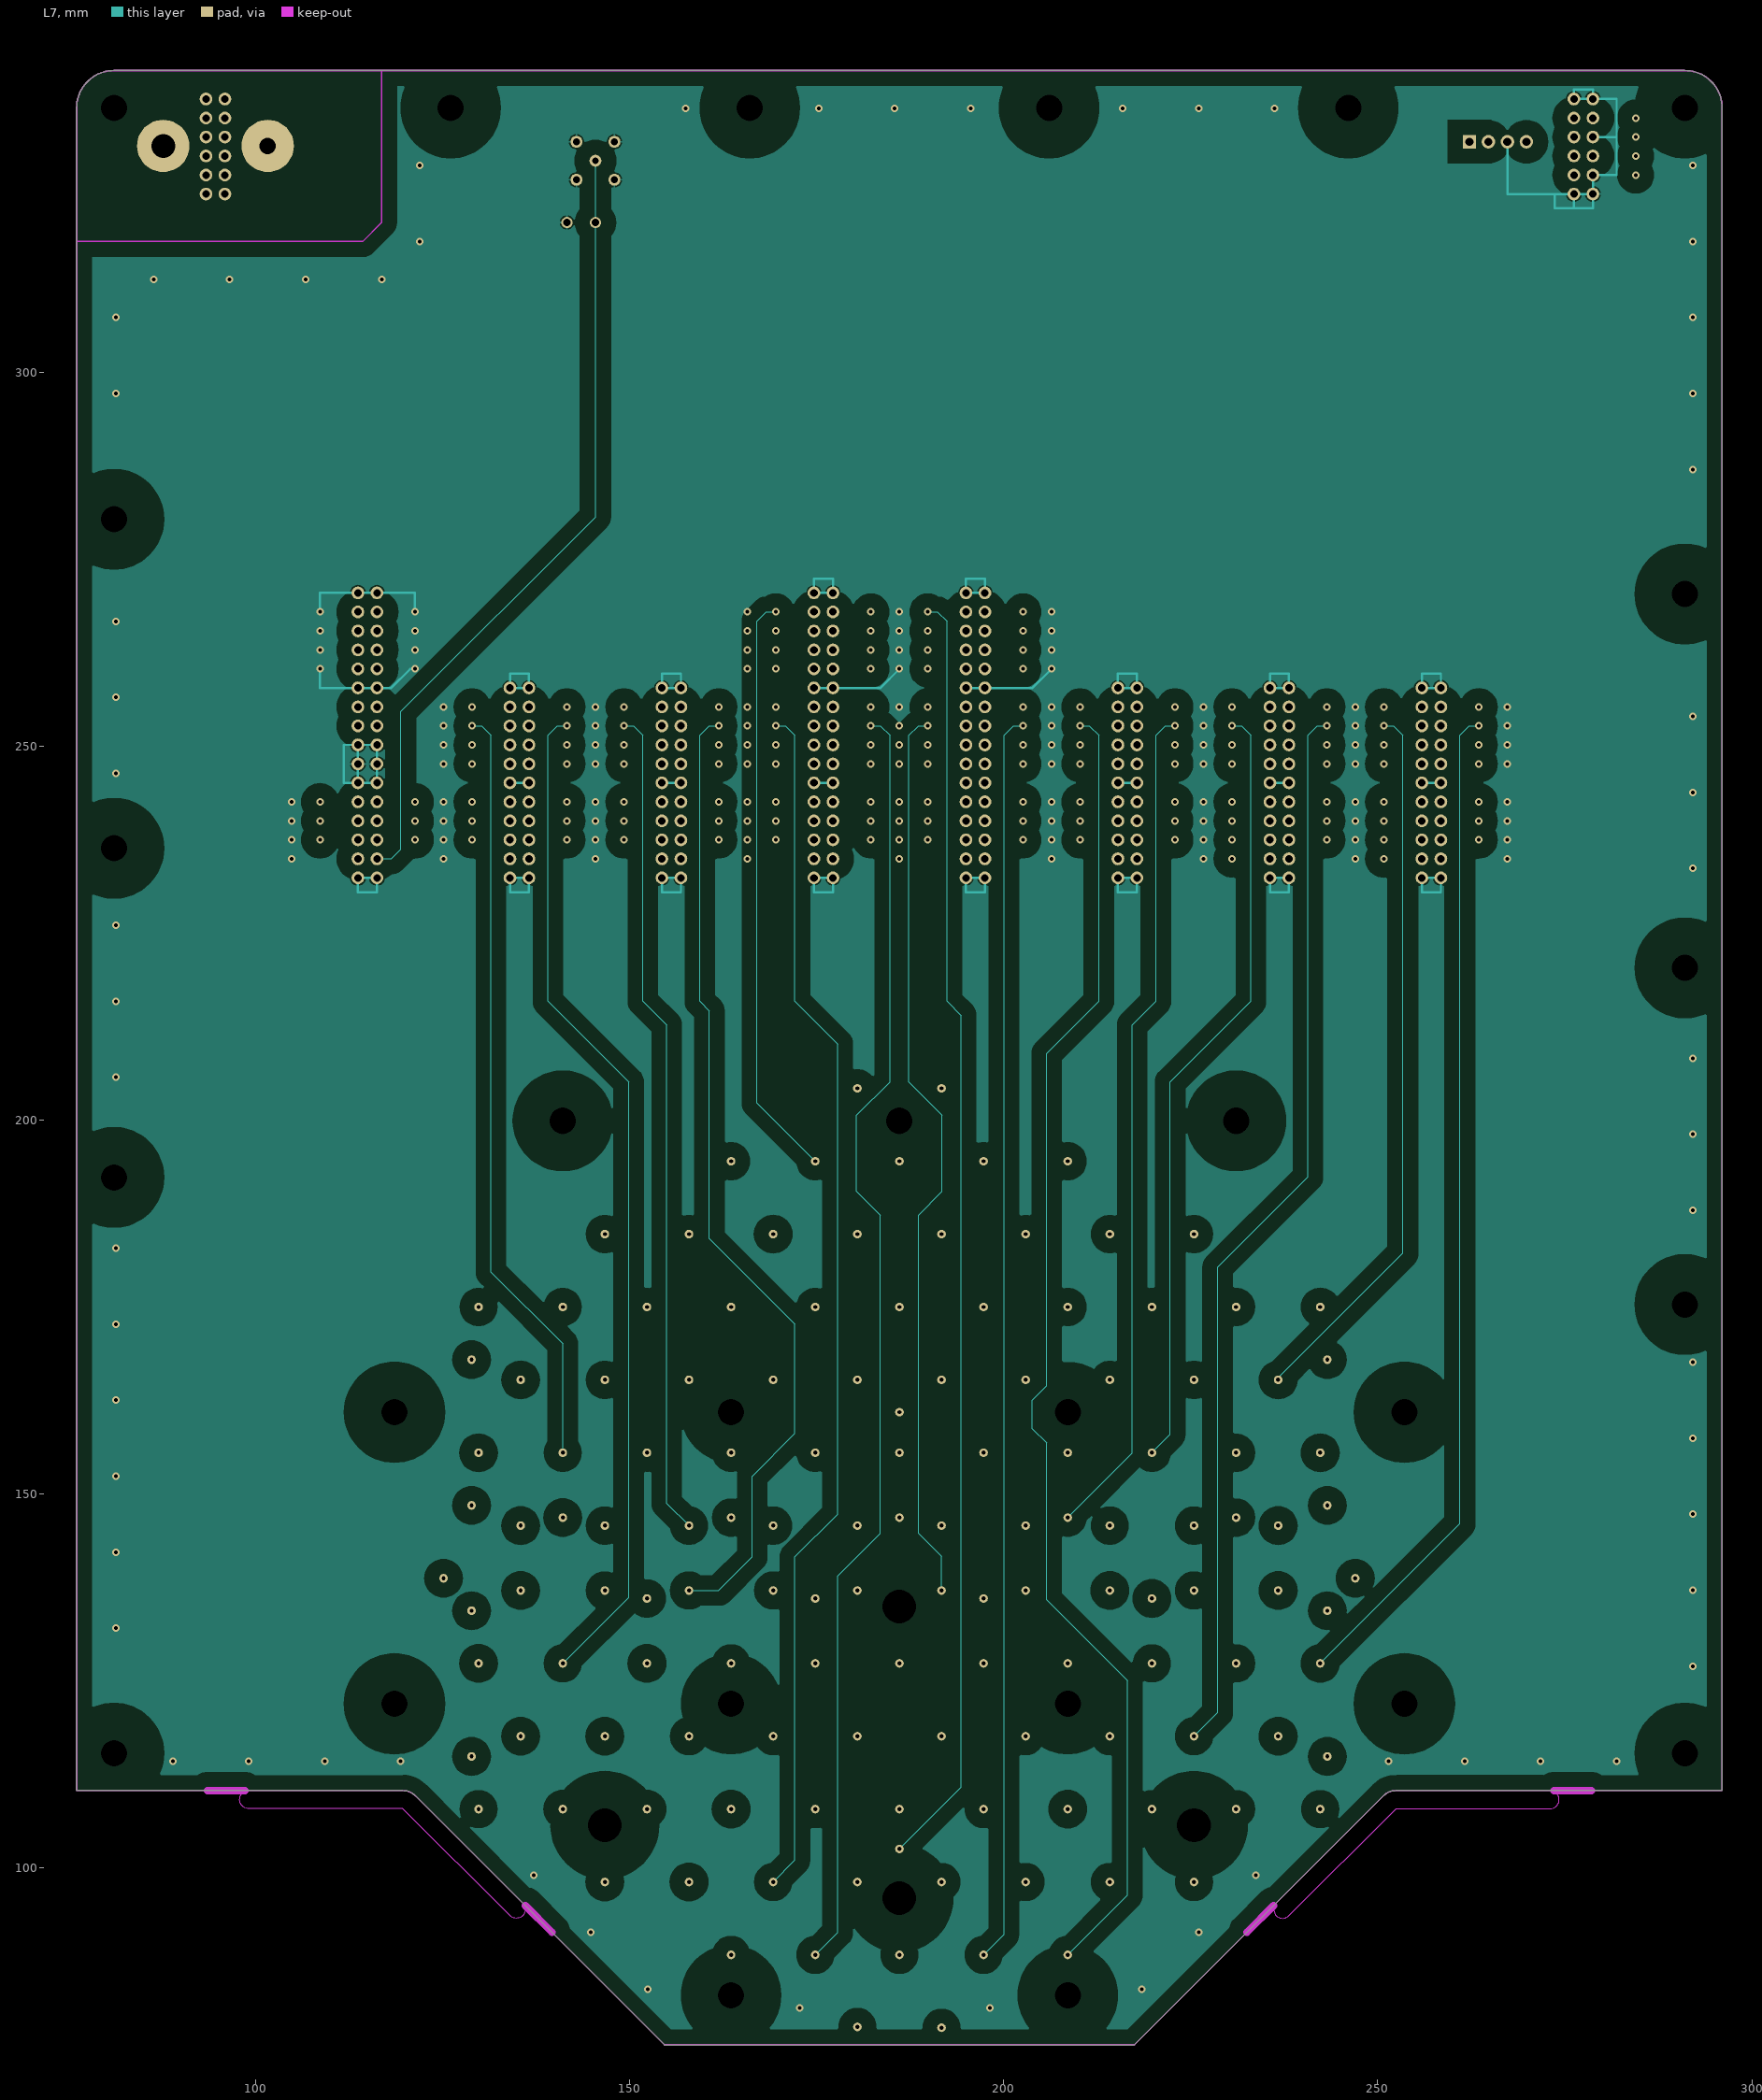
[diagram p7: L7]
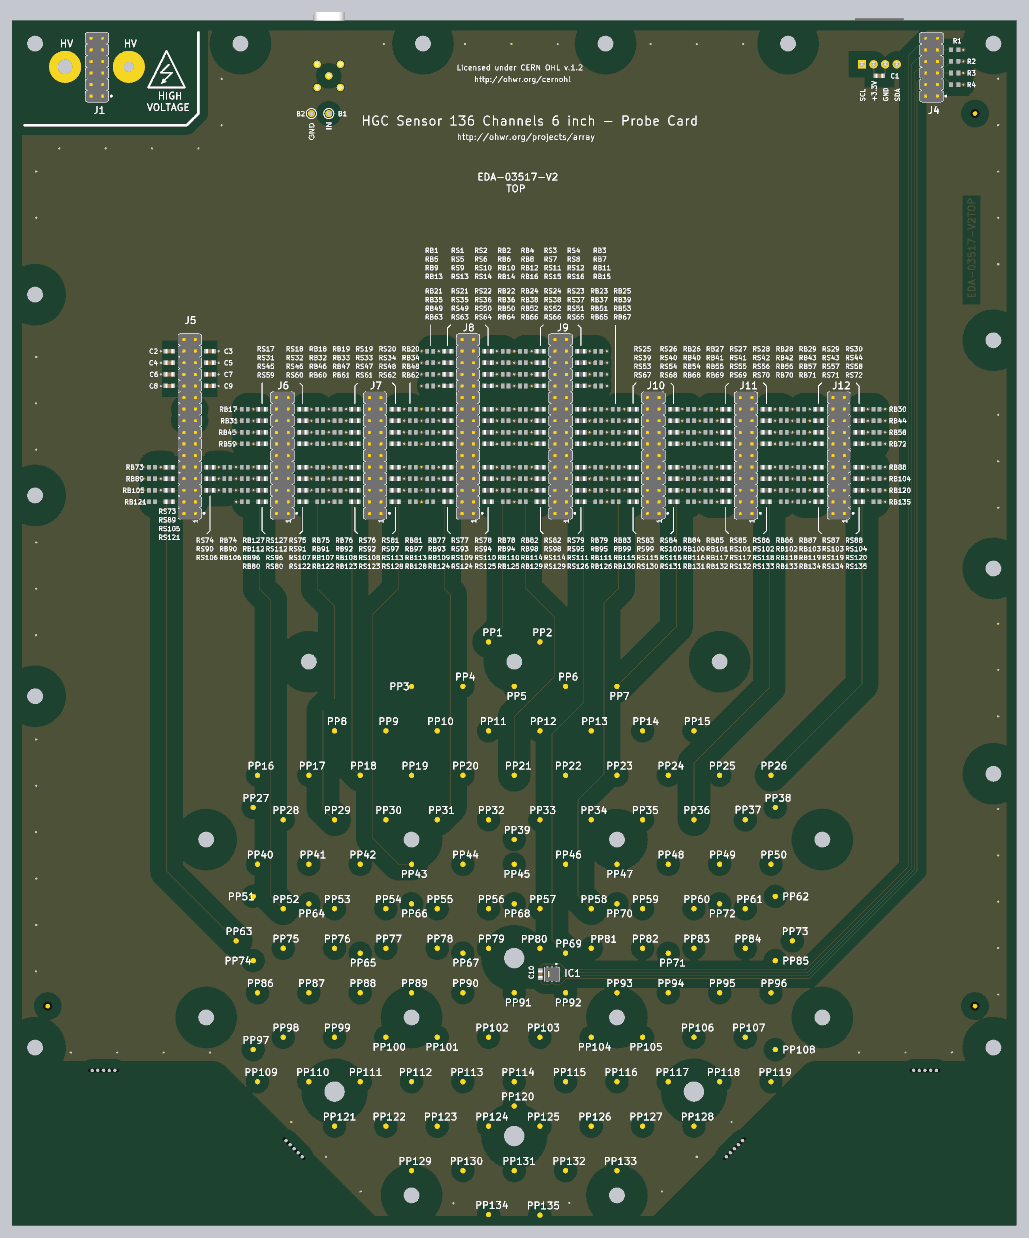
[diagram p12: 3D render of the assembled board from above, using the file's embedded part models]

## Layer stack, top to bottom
Top Solder: solder mask 0.01, Solder Resist, Dk 3.5
Top Layer: signal copper 0.035
Dielectric 1: prepreg 0.2, FR-4, Dk 4.5
L2: signal copper 0.035
Dielectric 3: core 0.2, Dk 4.2
L3: signal copper 0.035
Dielectric 6: prepreg 0.2, FR-4, Dk 4.2
L4: signal copper 0.035
Dielectric 5: core 0.7, Dk 4.2
L5: signal copper 0.035
Dielectric 4: prepreg 0.2, FR-4, Dk 4.2
L6: signal copper 0.035
Dielectric 7: core 0.2, Dk 4.2
L7: signal copper 0.035
Dielectric 8: prepreg 0.2, FR-4, Dk 4.2
Bottom Layer: signal copper 0.035
Bottom Solder: solder mask 0.01, Solder Resist, Dk 3.5

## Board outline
76.055,110.36 76.055,335.36 cw(c81.055,335.36) 81.055,340.36 291.055,340.36 cw(c291.055,335.36) 296.055,335.36 296.055,110.36 252.449,110.36 ccw(c252.449,107.96) 250.752,109.657 217.455,76.36 154.655,76.36 121.358,109.657 ccw(c119.661,107.96) 119.661,110.36
cut-out: 236.434,95.339 ccw(c237.282,94.49) 238.131,93.641 252.449,107.96 273.055,107.96 ccw(c273.055,109.16) 273.055,110.36 252.449,110.36 ccw(c252.449,107.96) 250.752,109.657
cut-out: 99.055,107.96 cw(c99.055,109.16) 99.055,110.36 119.661,110.36 cw(c119.661,107.96) 121.358,109.657 135.685,95.33 cw(c134.837,94.481) 133.988,93.633 119.661,107.96

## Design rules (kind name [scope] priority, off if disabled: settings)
BoardOutlineClearance "Via Tenting" [IsVia and ((SolderMaskTentingTop='False') or (SolderMaskTentingBottom='False'))] p1: gap=2500 ignorepadtopadclearanceinfootprint=FALSE
BoardOutlineClearance "Inverted Serig" [((ObjectKind = 'Text') And (IsTextInverted = 'True')) And ((AsMM(InvertedTextBorder) < 0.2) or (AsMM(TextHeight) < 1.5))] p2: gap=2500 ignorepadtopadclearanceinfootprint=FALSE
BoardOutlineClearance "Uncheck Plat" [(PadIsPlated = 'True') And ((HoleDiameter >= PadXSize_AllLayers ) OR (HoleDiameter >= PadYSize_AllLayers))] p3: gap=2500 ignorepadtopadclearanceinfootprint=FALSE
BoardOutlineClearance "Defaut Serig" [(((Layer = 'TopOverlay')  And (StrokeFont = 'Default')) or ((Layer = 'BottomOverlay')  And (StrokeFont = 'Default'))) and not IsTextInverted = 'True'] p4: gap=2500 ignorepadtopadclearanceinfootprint=FALSE
Clearance Clearance_Panel [InPadClass('Panel') vs OnLayer('Keep-Out Layer')] p1: gap=0 ignorepadtopadclearanceinfootprint=FALSE
Clearance Clearance_HV [InNet('HV') vs InNet('GND')] p2: gap=3.5 ignorepadtopadclearanceinfootprint=FALSE // HV <> GND
Clearance Clearance_PolyMount_Ext [InPadClass('Mounting') or InPolygon vs (IsTrack and InNetClass('PP')) and (OnLayer('Top Layer') or OnLayer('Bottom Layer'))] p3: gap=3.5 ignorepadtopadclearanceinfootprint=FALSE except(1: Fill-Text Poly-Text Region-Text) // Poly et Mounting  <> Pistes PP sur Top et Bot
Clearance Clearance_Poly2Mount [InPolygon vs InPadClass('Mounting')] p4: gap=5 ignorepadtopadclearanceinfootprint=FALSE
Clearance Clearance_PolyMount2All [InPadClass('Mounting') or InPolygon] p5: gap=2 ignorepadtopadclearanceinfootprint=FALSE except(1: Fill-Text Poly-Text Region-Text) // Poly et Mounting  <> All
Clearance Clearance_PP_Tracks [(InNetClass('PP') and not (IsSMTPin or isvia)) vs (InNetClass('PP') and not (IsSMTPin or isvia))] p6: gap=1.5 ignorepadtopadclearanceinfootprint=FALSE // Entre Nets PP (uniquement les Tracks)
Clearance Clearance_PP [InNetClass('PP') vs InNetClass('PP')] p7: gap=1.5 ignorepadtopadclearanceinfootprint=FALSE // Entre Nets PP
Clearance Clearance_Mires [OnLayer('Keep-Out Layer') vs HasFootprint('FIDUCIAL_TOP_S100-200')] p8: gap=0 ignorepadtopadclearanceinfootprint=FALSE except(4.9: Arc-SMDPad Track-SMDPad) // Mires to Bord de carte Keep-Out
Clearance [All] p9: gap=0.3 ignorepadtopadclearanceinfootprint=FALSE
ComponentClearance ComponentClearance_Overlapping [InComponentClass('Overlapping') or InComponentClass('NotMounted') vs InComponentClass('Overlapping')] p1: gap=0 collisioncheckmode=3 verticalgap=0 showdistances=FALSE
ComponentClearance [not InComponentClass('Overlapping')] p2: gap=0.2 collisioncheckmode=3 verticalgap=0.2 showdistances=FALSE
DiffPairsRouting [All] p1: maxlimit=0.457 minlimit=0.457 mostfreqgap=0.457 toplayer_minwidth=0.229 toplayer_maxwidth=0.229 toplayer_prefwidth=0.229 midlayer1_minwidth=0.229 midlayer1_maxwidth=0.229 midlayer1_prefwidth=0.229 midlayer2_minwidth=0.229 midlayer2_maxwidth=0.229 midlayer2_prefwidth=0.229 midlayer3_minwidth=0.229 midlayer3_maxwidth=0.229 midlayer3_prefwidth=0.229 midlayer4_minwidth=0.229 midlayer4_maxwidth=0.229 midlayer4_prefwidth=0.229 midlayer5_minwidth=0.229 midlayer5_maxwidth=0.229 midlayer5_prefwidth=0.229 midlayer6_minwidth=0.229 midlayer6_maxwidth=0.229 midlayer6_prefwidth=0.229 bottomlayer_minwidth=0.229 bottomlayer_maxwidth=0.229 bottomlayer_prefwidth=0.229 maxuncoupledlength=2.54
FabricationTestPointUsage TestPointUsage [All] p1: valid=0 allowmultiple=FALSE
FabricationTestpoint Testpoint [All] p1: side=3 testpointundercomponent=TRUE minsize=1.016 maxsize=2.54 preferedsize=1.524 minholesize=0 maxholesize=1.016 preferedholesize=0.813 testpointgrid=0.025 allowsidetop=TRUE allowsidebottom=TRUE usegrid=TRUE gridtolerance=0
Height [All] p1: minheight=0 maxheight=25 prefheight=10
HoleSize [All] p1: absolutevalues=TRUE maxlimit=5 minlimit=0.4 maxpercent=80.000 minpercent=20.000
HoleToHoleClearance [All] p1: gap=0.2 allowstackedmicrovias=TRUE
MinimumSolderMaskSliver [All] p1: minsoldermaskwidth=0.35
PermittedLayers [All] p1: toplayerpermitted=TRUE bottomlayerpermitted=TRUE
PlaneClearance [All] p1: clearance=0.5
PlaneConnect PlaneConnect_Direct [InPadClass('Mounting') or IsVia] p1: planeconnectstyle=Direct reliefexpansion=0.508 reliefentries=4 reliefconductorwidth=0.254 reliefairgap=0.254
PlaneConnect "PlaneConnect_0 > 1" [(AsMM(HoleDiameter)<1)] p2: planeconnectstyle=Relief reliefexpansion=0.3 reliefentries=4 reliefconductorwidth=0.25 reliefairgap=0.2
PlaneConnect "PlaneConnect_1 > 1.5" [(AsMM(HoleDiameter)>=1) and (AsMM(HoleDiameter)<1.5)] p3: planeconnectstyle=Relief reliefexpansion=0.3 reliefentries=4 reliefconductorwidth=0.3 reliefairgap=0.2
PlaneConnect "PlaneConnect_1.5 > 2" [(AsMM(HoleDiameter)>=1.5) and (AsMM(HoleDiameter)<2)] p4: planeconnectstyle=Relief reliefexpansion=0.3 reliefentries=4 reliefconductorwidth=0.4 reliefairgap=0.2
PlaneConnect [All] p5: planeconnectstyle=Relief reliefexpansion=0.3 reliefentries=4 reliefconductorwidth=0.5 reliefairgap=0.2
PolygonConnect PolygonConnect_Direct [InPadClass('Mounting') or IsVia] p1: connectstyle=Direct reliefconductorwidth=0.254 reliefentries=4 polygonreliefangle="90 Angle" airgapwidth=0.254
PolygonConnect "PolygonConnect_0 > 1" [(AsMM(HoleDiameter)<1)] p2: connectstyle=Relief reliefconductorwidth=0.25 reliefentries=4 polygonreliefangle="90 Angle" airgapwidth=0.2
PolygonConnect "PolygonConnect_1 > 1.5" [(AsMM(HoleDiameter)>=1) and (AsMM(HoleDiameter)<1.5)] p3: connectstyle=Relief reliefconductorwidth=0.3 reliefentries=4 polygonreliefangle="90 Angle" airgapwidth=0.2
PolygonConnect "PolygonConnect_1.5 > 2" [(AsMM(HoleDiameter)>=1.5) and (AsMM(HoleDiameter)<2)] p4: connectstyle=Relief reliefconductorwidth=0.4 reliefentries=4 polygonreliefangle="90 Angle" airgapwidth=0.2
PolygonConnect [All] p5: connectstyle=Relief reliefconductorwidth=0.5 reliefentries=4 polygonreliefangle="90 Angle" airgapwidth=0.2
RoomDefinition ProbeCard [InComponentClass('ProbeCard')] p1: confinementstyle=ConfineIn formatcopy=TRUE lockcomponents=FALSE outline 80.645,77.47 290.195,77.47 290.195,348.615 80.645,348.615
RoutingVias RoutingVias_NoNet [Not IsElectrical] p1: holewidth=0 width=0 viastyle="Through Hole" minholewidth=0 minwidth=0 maxholewidth=0 maxwidth=0
RoutingVias [All] p2: holewidth=0.5 width=1 viastyle="Through Hole" minholewidth=0.5 minwidth=1 maxholewidth=0.5 maxwidth=1
ShortCircuit ShortCircuit_NetTie [InNet('GND') vs InNet('VSS')or InNet('CGND')] p1: allowed=TRUE
ShortCircuit [All] p2: allowed=FALSE
SilkToSilkClearance [All] p1: silktosilkclearance=0.2
SilkToSolderMaskClearance SilkToSolderMaskClearanceVias [IsVia vs IsText] p1: minsilkscreentomaskgap=0 clearancetoexposedcopper=TRUE
SilkToSolderMaskClearance SilkscreenOverComponentPads [IsPad] p2: minsilkscreentomaskgap=0.225 clearancetoexposedcopper=TRUE
SolderMaskExpansion [All] p1: expansion=0
ViasUnderSMD [Not HasFootprint('Net Tie')] p1: allowed=FALSE
Width [All] p1: maxlimit=2.54 minlimit=0.152 preferedwidth=0.152
17 further rules are at their usual default settings.

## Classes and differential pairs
pad class Panel: Free-P80NP
pad class Mounting: Free-D350NP Free-P450NP
component class Overlapping: J4
component class NotMounted: NT1 NT2 R1 R2 R3 R4 RB1 RB2 RB3 RB4 RB5 RB6 RB7 RB8 RB9 RB10 RB11 RB12 RB13 RB14 RB15 RB16 RB17 RB18 RB19 RB20 RB21 RB22 RB23 RB24 RB25 RB26 RB27 RB28 RB29 RB30 RB31 RB32 RB33 RB34 RB35 RB36 RB37 RB38 RB39 RB40 RB41 RB42 RB43 RB44 RB45 RB46 RB47 RB48 RB49 RB50 RB51 RB52 RB53 RB54 RB55 RB56 RB57 RB58 RB59 RB60 RB61 RB62 RB63 RB64 RB65 RB66 RB67 RB68 RB69 RB70 RB71 RB72 RB73 RB74 RB75 RB76 RB77 RB78 RB79 RB80 RB81 RB82 RB83 RB84 RB85 RB86 RB87 RB88 RB89 RB90 RB91 RB92 RB93 RB94 RB95 RB96 RB97 RB98 RB99 RB100 RB101 RB102 RB103 RB104 RB105 RB106 RB107 RB108 RB109 RB110 RB111 RB112 RB113 RB114 RB115 RB116 RB117 RB118 RB119 RB120 RB121 RB122 RB123 RB124 RB125 RB126 RB127 RB128 RB129 RB130 RB131 RB132 RB133 RB134 RB135
net class PP: NetPP1_1 NetPP2_1 NetPP3_1 NetPP4_1 NetPP5_1 NetPP6_1 NetPP7_1 NetPP8_1 NetPP9_1 NetPP10_1 NetPP11_1 NetPP12_1 NetPP13_1 NetPP14_1 NetPP15_1 NetPP16_1 NetPP17_1 NetPP18_1 NetPP19_1 NetPP20_1 NetPP21_1 NetPP22_1 NetPP23_1 NetPP24_1 NetPP25_1 NetPP26_1 NetPP27_1 NetPP28_1 NetPP29_1 NetPP30_1 NetPP31_1 NetPP32_1 NetPP33_1 NetPP34_1 NetPP35_1 NetPP36_1 NetPP37_1 NetPP38_1 NetPP39_1 NetPP40_1 NetPP41_1 NetPP42_1 NetPP43_1 NetPP44_1 NetPP45_1 NetPP46_1 NetPP47_1 NetPP48_1 NetPP49_1 NetPP50_1 NetPP51_1 NetPP52_1 NetPP53_1 NetPP54_1 NetPP55_1 NetPP56_1 NetPP57_1 NetPP58_1 NetPP59_1 NetPP60_1 NetPP61_1 NetPP62_1 NetPP63_1 NetPP64_1 NetPP65_1 NetPP66_1 NetPP67_1 NetPP68_1 NetPP69_1 NetPP70_1 NetPP71_1 NetPP72_1 NetPP73_1 NetPP74_1 NetPP75_1 NetPP76_1 NetPP77_1 NetPP78_1 NetPP79_1 NetPP80_1 NetPP81_1 NetPP82_1 NetPP83_1 NetPP84_1 NetPP85_1 NetPP86_1 NetPP87_1 NetPP88_1 NetPP89_1 NetPP90_1 NetPP91_1 NetPP92_1 NetPP93_1 NetPP94_1 NetPP95_1 NetPP96_1 NetPP97_1 NetPP98_1 NetPP99_1 NetPP100_1 NetPP101_1 NetPP102_1 NetPP103_1 NetPP104_1 NetPP105_1 NetPP106_1 NetPP107_1 NetPP108_1 NetPP109_1 NetPP110_1 NetPP111_1 NetPP112_1 NetPP113_1 NetPP114_1 NetPP115_1 NetPP116_1 NetPP117_1 NetPP118_1 NetPP119_1 NetPP120_1 NetPP121_1 NetPP122_1 NetPP123_1 NetPP124_1 NetPP125_1 NetPP126_1 NetPP127_1 NetPP128_1 NetPP129_1 NetPP130_1 NetPP131_1 NetPP132_1 NetPP133_1 NetPP134_1 NetPP135_1

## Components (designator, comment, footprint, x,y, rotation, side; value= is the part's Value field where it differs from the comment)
B1 "IN" c150h100 145.415,320.04 r0 top
B2 "GND" c150h100 141.605,320.04 r0 top
C1 "100nF" CAPC1608X87N 266.065,328.295 r180 top
C2 "1pF" CAPC1608X87N 110.49,267.97 r180 top
C3 "2.2pF" CAPC1608X87N 119.38,267.97 r0 top
C4 "4.7pF" CAPC1608X87N 110.49,265.43 r180 top
C5 "10pF" CAPC1608X87N 119.38,265.43 r0 top
C6 "22pF" CAPC1608X87N 110.49,262.89 r180 top
C7 "47pF" CAPC1608X87N 119.38,262.89 r0 top
C8 "100pF" CAPC1608X87N 110.49,260.35 r180 top
C9 "220pF" CAPC1608X87N 119.38,260.35 r0 top
C10 "100nF" CAPC1608X87N 191.77,131.445 r270 top
FTG1 "Use only in PCB" FIDUCIAL_TOP_C100-200 287.02,320.04 r0 top
FTG2 "Use only in PCB" FIDUCIAL_TOP_C100-200 83.82,124.46 r0 top
FTG3 "Use only in PCB" FIDUCIAL_TOP_C100-200 287.02,124.46 r0 top
IC1 "SHT25" SENSIRION_SHT2X 194.31,131.445 r90 top
J1 "Header 12" SAMTEC_MTLW-106-07-L-D-250 94.615,330.2 r90 top
J2 "LEMO 00" LEMO_EPK.00.250.NTN 145.415,328.295 r90 bottom
J3 "Socket 4" SAMTEC_SSW-104-02-L-S-RA 266.065,330.835 r180 bottom
J4 "Header 12" SAMTEC_MTLW-106-07-L-D-250 277.495,330.2 r90 top
J5 "Header 32" SAMTEC_MTLW-116-07-L-D-250 114.935,251.46 r90 top
J6 "Header 22" SAMTEC_MTLW-111-07-L-D-250 135.255,245.11 r90 top
J7 "Header 22" SAMTEC_MTLW-111-07-L-D-250 155.575,245.11 r90 top
J8 "Header 32" SAMTEC_MTLW-116-07-L-D-250 175.895,251.46 r90 top
J9 "Header 32" SAMTEC_MTLW-116-07-L-D-250 196.215,251.46 r90 top
J10 "Header 22" SAMTEC_MTLW-111-07-L-D-250 216.535,245.11 r90 top
J11 "Header 22" SAMTEC_MTLW-111-07-L-D-250 236.855,245.11 r90 top
J12 "Header 22" SAMTEC_MTLW-111-07-L-D-250 257.175,245.11 r90 top
NT1 "Net Tie" "Net Tie" 275.41,335.735 r45 top net-tie
NT2 "Net Tie" "Net Tie" 267.335,329.565 r270 top net-tie
PP1 "Probe" MILL-MAX_0985-1-15-20-71-14-11-0 180.429,204.261 r0 bottom
PP2 "Probe" MILL-MAX_0985-1-15-20-71-14-11-0 191.681,204.261 r0 bottom
PP3 "Probe" MILL-MAX_0985-1-15-20-71-14-11-0 163.551,194.516 r0 bottom
PP4 "Probe" MILL-MAX_0985-1-15-20-71-14-11-0 174.803,194.516 r0 bottom
PP5 "Probe" MILL-MAX_0985-1-15-20-71-14-11-0 186.055,194.516 r0 bottom
PP6 "Probe" MILL-MAX_0985-1-15-20-71-14-11-0 197.307,194.516 r0 bottom
PP7 "Probe" MILL-MAX_0985-1-15-20-71-14-11-0 208.559,194.516 r0 bottom
PP8 "Probe" MILL-MAX_0985-1-15-20-71-14-11-0 146.673,184.772 r0 bottom
PP9 "Probe" MILL-MAX_0985-1-15-20-71-14-11-0 157.925,184.772 r0 bottom
PP10 "Probe" MILL-MAX_0985-1-15-20-71-14-11-0 169.177,184.772 r0 bottom
PP11 "Probe" MILL-MAX_0985-1-15-20-71-14-11-0 180.429,184.772 r0 bottom
PP12 "Probe" MILL-MAX_0985-1-15-20-71-14-11-0 191.681,184.772 r0 bottom
PP13 "Probe" MILL-MAX_0985-1-15-20-71-14-11-0 202.933,184.772 r0 bottom
PP14 "Probe" MILL-MAX_0985-1-15-20-71-14-11-0 214.185,184.772 r0 bottom
PP15 "Probe" MILL-MAX_0985-1-15-20-71-14-11-0 225.437,184.772 r0 bottom
PP16 "Probe" MILL-MAX_0985-1-15-20-71-14-11-0 129.795,175.027 r0 bottom
PP17 "Probe" MILL-MAX_0985-1-15-20-71-14-11-0 141.047,175.027 r0 bottom
PP18 "Probe" MILL-MAX_0985-1-15-20-71-14-11-0 152.299,175.027 r0 bottom
PP19 "Probe" MILL-MAX_0985-1-15-20-71-14-11-0 163.551,175.027 r0 bottom
PP20 "Probe" MILL-MAX_0985-1-15-20-71-14-11-0 174.803,175.027 r0 bottom
PP21 "Probe" MILL-MAX_0985-1-15-20-71-14-11-0 186.055,175.027 r0 bottom
PP22 "Probe" MILL-MAX_0985-1-15-20-71-14-11-0 197.307,175.027 r0 bottom
PP23 "Probe" MILL-MAX_0985-1-15-20-71-14-11-0 208.559,175.027 r0 bottom
PP24 "Probe" MILL-MAX_0985-1-15-20-71-14-11-0 219.811,175.027 r0 bottom
PP25 "Probe" MILL-MAX_0985-1-15-20-71-14-11-0 231.063,175.027 r0 bottom
PP26 "Probe" MILL-MAX_0985-1-15-20-71-14-11-0 242.315,175.027 r0 bottom
PP27 "Probe" MILL-MAX_0985-1-15-20-71-14-11-0 128.852,167.986 r0 bottom
PP28 "Probe" MILL-MAX_0985-1-15-20-71-14-11-0 135.421,165.283 r0 bottom
PP29 "Probe" MILL-MAX_0985-1-15-20-71-14-11-0 146.673,165.283 r0 bottom
PP30 "Probe" MILL-MAX_0985-1-15-20-71-14-11-0 157.925,165.283 r0 bottom
PP31 "Probe" MILL-MAX_0985-1-15-20-71-14-11-0 169.177,165.283 r0 bottom
PP32 "Probe" MILL-MAX_0985-1-15-20-71-14-11-0 180.429,165.283 r0 bottom
PP33 "Probe" MILL-MAX_0985-1-15-20-71-14-11-0 191.681,165.283 r0 bottom
PP34 "Probe" MILL-MAX_0985-1-15-20-71-14-11-0 202.933,165.283 r0 bottom
PP35 "Probe" MILL-MAX_0985-1-15-20-71-14-11-0 214.185,165.283 r0 bottom
PP36 "Probe" MILL-MAX_0985-1-15-20-71-14-11-0 225.437,165.283 r0 bottom
PP37 "Probe" MILL-MAX_0985-1-15-20-71-14-11-0 236.689,165.283 r0 bottom
PP38 "Probe" MILL-MAX_0985-1-15-20-71-14-11-0 243.258,167.986 r0 bottom
PP39 "Probe" MILL-MAX_0985-1-15-20-71-14-11-0 186.055,160.96 r0 bottom
PP40 "Probe" MILL-MAX_0985-1-15-20-71-14-11-0 129.795,155.538 r0 bottom
PP41 "Probe" MILL-MAX_0985-1-15-20-71-14-11-0 141.047,155.538 r0 bottom
PP42 "Probe" MILL-MAX_0985-1-15-20-71-14-11-0 152.299,155.538 r0 bottom
PP43 "Probe" MILL-MAX_0985-1-15-20-71-14-11-0 163.551,155.538 r0 bottom
PP44 "Probe" MILL-MAX_0985-1-15-20-71-14-11-0 174.803,155.538 r0 bottom
PP45 "Probe" MILL-MAX_0985-1-15-20-71-14-11-0 186.055,155.538 r0 bottom
PP46 "Probe" MILL-MAX_0985-1-15-20-71-14-11-0 197.307,155.538 r0 bottom
PP47 "Probe" MILL-MAX_0985-1-15-20-71-14-11-0 208.559,155.538 r0 bottom
PP48 "Probe" MILL-MAX_0985-1-15-20-71-14-11-0 219.811,155.538 r0 bottom
PP49 "Probe" MILL-MAX_0985-1-15-20-71-14-11-0 231.063,155.538 r0 bottom
PP50 "Probe" MILL-MAX_0985-1-15-20-71-14-11-0 242.315,155.538 r0 bottom
PP51 "Probe" MILL-MAX_0985-1-15-20-71-14-11-0 128.852,148.497 r0 bottom
PP52 "Probe" MILL-MAX_0985-1-15-20-71-14-11-0 135.421,145.794 r0 bottom
PP53 "Probe" MILL-MAX_0985-1-15-20-71-14-11-0 146.673,145.794 r0 bottom
PP54 "Probe" MILL-MAX_0985-1-15-20-71-14-11-0 157.925,145.794 r0 bottom
PP55 "Probe" MILL-MAX_0985-1-15-20-71-14-11-0 169.177,145.794 r0 bottom
PP56 "Probe" MILL-MAX_0985-1-15-20-71-14-11-0 180.429,145.794 r0 bottom
PP57 "Probe" MILL-MAX_0985-1-15-20-71-14-11-0 191.681,145.794 r0 bottom
PP58 "Probe" MILL-MAX_0985-1-15-20-71-14-11-0 202.933,145.794 r0 bottom
PP59 "Probe" MILL-MAX_0985-1-15-20-71-14-11-0 214.185,145.794 r0 bottom
PP60 "Probe" MILL-MAX_0985-1-15-20-71-14-11-0 225.437,145.794 r0 bottom
PP61 "Probe" MILL-MAX_0985-1-15-20-71-14-11-0 236.689,145.794 r0 bottom
PP62 "Probe" MILL-MAX_0985-1-15-20-71-14-11-0 243.258,148.497 r0 bottom
PP63 "Probe" MILL-MAX_0985-1-15-20-71-14-11-0 125.112,138.753 r0 bottom
PP64 "Probe" MILL-MAX_0985-1-15-20-71-14-11-0 141.047,146.864 r0 bottom
PP65 "Probe" MILL-MAX_0985-1-15-20-71-14-11-0 152.299,136.049 r0 bottom
PP66 "Probe" MILL-MAX_0985-1-15-20-71-14-11-0 163.551,146.864 r0 bottom
PP67 "Probe" MILL-MAX_0985-1-15-20-71-14-11-0 174.803,136.049 r0 bottom
PP68 "Probe" MILL-MAX_0985-1-15-20-71-14-11-0 186.055,146.864 r0 bottom
PP69 "Probe" MILL-MAX_0985-1-15-20-71-14-11-0 197.307,136.049 r0 bottom
PP70 "Probe" MILL-MAX_0985-1-15-20-71-14-11-0 208.559,146.864 r0 bottom
PP71 "Probe" MILL-MAX_0985-1-15-20-71-14-11-0 219.811,136.049 r0 bottom
PP72 "Probe" MILL-MAX_0985-1-15-20-71-14-11-0 231.063,146.864 r0 bottom
PP73 "Probe" MILL-MAX_0985-1-15-20-71-14-11-0 246.998,138.753 r0 bottom
PP74 "Probe" MILL-MAX_0985-1-15-20-71-14-11-0 128.852,134.415 r0 bottom
PP75 "Probe" MILL-MAX_0985-1-15-20-71-14-11-0 135.421,137.119 r0 bottom
PP76 "Probe" MILL-MAX_0985-1-15-20-71-14-11-0 146.673,137.119 r0 bottom
PP77 "Probe" MILL-MAX_0985-1-15-20-71-14-11-0 157.925,137.119 r0 bottom
PP78 "Probe" MILL-MAX_0985-1-15-20-71-14-11-0 169.177,137.119 r0 bottom
PP79 "Probe" MILL-MAX_0985-1-15-20-71-14-11-0 180.429,137.119 r0 bottom
PP80 "Probe" MILL-MAX_0985-1-15-20-71-14-11-0 191.681,137.119 r0 bottom
PP81 "Probe" MILL-MAX_0985-1-15-20-71-14-11-0 202.933,137.119 r0 bottom
PP82 "Probe" MILL-MAX_0985-1-15-20-71-14-11-0 214.185,137.119 r0 bottom
PP83 "Probe" MILL-MAX_0985-1-15-20-71-14-11-0 225.437,137.119 r0 bottom
PP84 "Probe" MILL-MAX_0985-1-15-20-71-14-11-0 236.689,137.119 r0 bottom
PP85 "Probe" MILL-MAX_0985-1-15-20-71-14-11-0 243.258,134.415 r0 bottom
PP86 "Probe" MILL-MAX_0985-1-15-20-71-14-11-0 129.795,127.375 r0 bottom
PP87 "Probe" MILL-MAX_0985-1-15-20-71-14-11-0 141.047,127.375 r0 bottom
PP88 "Probe" MILL-MAX_0985-1-15-20-71-14-11-0 152.299,127.375 r0 bottom
PP89 "Probe" MILL-MAX_0985-1-15-20-71-14-11-0 163.551,127.375 r0 bottom
PP90 "Probe" MILL-MAX_0985-1-15-20-71-14-11-0 174.803,127.375 r0 bottom
PP91 "Probe" MILL-MAX_0985-1-15-20-71-14-11-0 186.055,127.375 r0 bottom
PP92 "Probe" MILL-MAX_0985-1-15-20-71-14-11-0 197.307,127.375 r0 bottom
PP93 "Probe" MILL-MAX_0985-1-15-20-71-14-11-0 208.559,127.375 r0 bottom
PP94 "Probe" MILL-MAX_0985-1-15-20-71-14-11-0 219.811,127.375 r0 bottom
PP95 "Probe" MILL-MAX_0985-1-15-20-71-14-11-0 231.063,127.375 r0 bottom
PP96 "Probe" MILL-MAX_0985-1-15-20-71-14-11-0 242.315,127.375 r0 bottom
PP97 "Probe" MILL-MAX_0985-1-15-20-71-14-11-0 128.852,114.926 r0 bottom
PP98 "Probe" MILL-MAX_0985-1-15-20-71-14-11-0 135.421,117.63 r0 bottom
PP99 "Probe" MILL-MAX_0985-1-15-20-71-14-11-0 146.673,117.63 r0 bottom
PP100 "Probe" MILL-MAX_0985-1-15-20-71-14-11-0 157.925,117.63 r0 bottom
PP101 "Probe" MILL-MAX_0985-1-15-20-71-14-11-0 169.177,117.63 r0 bottom
PP102 "Probe" MILL-MAX_0985-1-15-20-71-14-11-0 180.429,117.63 r0 bottom
PP103 "Probe" MILL-MAX_0985-1-15-20-71-14-11-0 191.681,117.63 r0 bottom
PP104 "Probe" MILL-MAX_0985-1-15-20-71-14-11-0 202.933,117.63 r0 bottom
PP105 "Probe" MILL-MAX_0985-1-15-20-71-14-11-0 214.185,117.63 r0 bottom
PP106 "Probe" MILL-MAX_0985-1-15-20-71-14-11-0 225.437,117.63 r0 bottom
PP107 "Probe" MILL-MAX_0985-1-15-20-71-14-11-0 236.689,117.63 r0 bottom
PP108 "Probe" MILL-MAX_0985-1-15-20-71-14-11-0 243.258,114.926 r0 bottom
PP109 "Probe" MILL-MAX_0985-1-15-20-71-14-11-0 129.795,107.886 r0 bottom
PP110 "Probe" MILL-MAX_0985-1-15-20-71-14-11-0 141.047,107.886 r0 bottom
PP111 "Probe" MILL-MAX_0985-1-15-20-71-14-11-0 152.299,107.886 r0 bottom
PP112 "Probe" MILL-MAX_0985-1-15-20-71-14-11-0 163.551,107.886 r0 bottom
PP113 "Probe" MILL-MAX_0985-1-15-20-71-14-11-0 174.803,107.886 r0 bottom
PP114 "Probe" MILL-MAX_0985-1-15-20-71-14-11-0 186.055,107.886 r0 bottom
PP115 "Probe" MILL-MAX_0985-1-15-20-71-14-11-0 197.307,107.886 r0 bottom
PP116 "Probe" MILL-MAX_0985-1-15-20-71-14-11-0 208.559,107.886 r0 bottom
PP117 "Probe" MILL-MAX_0985-1-15-20-71-14-11-0 219.811,107.886 r0 bottom
PP118 "Probe" MILL-MAX_0985-1-15-20-71-14-11-0 231.063,107.886 r0 bottom
PP119 "Probe" MILL-MAX_0985-1-15-20-71-14-11-0 242.315,107.886 r0 bottom
PP120 "Probe" MILL-MAX_0985-1-15-20-71-14-11-0 186.055,102.56 r0 bottom
PP121 "Probe" MILL-MAX_0985-1-15-20-71-14-11-0 146.673,98.141 r0 bottom
PP122 "Probe" MILL-MAX_0985-1-15-20-71-14-11-0 157.925,98.141 r0 bottom
PP123 "Probe" MILL-MAX_0985-1-15-20-71-14-11-0 169.177,98.141 r0 bottom
PP124 "Probe" MILL-MAX_0985-1-15-20-71-14-11-0 180.429,98.141 r0 bottom
PP125 "Probe" MILL-MAX_0985-1-15-20-71-14-11-0 191.681,98.141 r0 bottom
PP126 "Probe" MILL-MAX_0985-1-15-20-71-14-11-0 202.933,98.141 r0 bottom
PP127 "Probe" MILL-MAX_0985-1-15-20-71-14-11-0 214.185,98.141 r0 bottom
PP128 "Probe" MILL-MAX_0985-1-15-20-71-14-11-0 225.437,98.141 r0 bottom
PP129 "Probe" MILL-MAX_0985-1-15-20-71-14-11-0 163.551,88.397 r0 bottom
PP130 "Probe" MILL-MAX_0985-1-15-20-71-14-11-0 174.803,88.397 r0 bottom
PP131 "Probe" MILL-MAX_0985-1-15-20-71-14-11-0 186.055,88.397 r0 bottom
PP132 "Probe" MILL-MAX_0985-1-15-20-71-14-11-0 197.307,88.397 r0 bottom
PP133 "Probe" MILL-MAX_0985-1-15-20-71-14-11-0 208.559,88.397 r0 bottom
PP134 "Probe" MILL-MAX_0985-1-15-20-71-14-11-0 180.435,78.76 r0 bottom
PP135 "Probe" MILL-MAX_0985-1-15-20-71-14-11-0 191.681,78.652 r0 bottom
R1 "10k" RESC1608X55N 282.575,334.01 r0 top
R2 "10k" RESC1608X55N 282.575,331.47 r0 top
R3 "10k" RESC1608X55N 282.575,328.93 r0 top
R4 "10k" RESC1608X55N 282.575,326.39 r0 top
RB1 "10M" RESC1508X63N 167.64,267.97 r180 top
RB2 "10M" RESC1508X63N 184.15,267.97 r0 top
RB3 "10M" RESC1508X63N 204.47,267.97 r0 top
RB4 "10M" RESC1508X63N 187.96,267.97 r180 top
RB5 "10M" RESC1508X63N 167.64,265.43 r180 top
RB6 "10M" RESC1508X63N 184.15,265.43 r0 top
RB7 "10M" RESC1508X63N 204.47,265.43 r0 top
RB8 "10M" RESC1508X63N 187.96,265.43 r180 top
RB9 "10M" RESC1508X63N 167.64,262.89 r180 top
RB10 "10M" RESC1508X63N 184.15,262.89 r0 top
RB11 "10M" RESC1508X63N 204.47,262.89 r0 top
RB12 "10M" RESC1508X63N 187.96,262.89 r180 top
RB13 "10M" RESC1508X63N 167.64,260.35 r180 top
RB14 "10M" RESC1508X63N 184.15,260.35 r0 top
RB15 "10M" RESC1508X63N 204.47,260.35 r0 top
RB16 "10M" RESC1508X63N 187.96,260.35 r180 top
RB17 "10M" RESC1508X63N 127,255.27 r180 top
RB18 "10M" RESC1508X63N 143.51,255.27 r0 top
RB19 "10M" RESC1508X63N 147.32,255.27 r180 top
RB20 "10M" RESC1508X63N 163.83,255.27 r0 top
RB21 "10M" RESC1508X63N 167.64,255.27 r180 top
RB22 "10M" RESC1508X63N 184.15,255.27 r0 top
RB23 "10M" RESC1508X63N 204.47,255.27 r0 top
RB24 "10M" RESC1508X63N 187.96,255.27 r180 top
RB25 "10M" RESC1508X63N 208.28,255.27 r180 top
RB26 "10M" RESC1508X63N 224.79,255.27 r0 top
RB27 "10M" RESC1508X63N 228.6,255.27 r180 top
RB28 "10M" RESC1508X63N 245.11,255.27 r0 top
RB29 "10M" RESC1508X63N 248.92,255.27 r180 top
RB30 "10M" RESC1508X63N 265.43,255.27 r0 top
RB31 "10M" RESC1508X63N 127,252.73 r180 top
RB32 "10M" RESC1508X63N 143.51,252.73 r0 top
RB33 "10M" RESC1508X63N 147.32,252.73 r180 top
RB34 "10M" RESC1508X63N 163.83,252.73 r0 top
RB35 "10M" RESC1508X63N 167.64,252.73 r180 top
RB36 "10M" RESC1508X63N 184.15,252.73 r0 top
RB37 "10M" RESC1508X63N 204.47,252.73 r0 top
RB38 "10M" RESC1508X63N 187.96,252.73 r180 top
RB39 "10M" RESC1508X63N 208.28,252.73 r180 top
RB40 "10M" RESC1508X63N 224.79,252.73 r0 top
RB41 "10M" RESC1508X63N 228.6,252.73 r180 top
RB42 "10M" RESC1508X63N 245.11,252.73 r0 top
RB43 "10M" RESC1508X63N 248.92,252.73 r180 top
RB44 "10M" RESC1508X63N 265.43,252.73 r0 top
RB45 "10M" RESC1508X63N 127,250.19 r180 top
RB46 "10M" RESC1508X63N 143.51,250.19 r0 top
RB47 "10M" RESC1508X63N 147.32,250.19 r180 top
RB48 "10M" RESC1508X63N 163.83,250.19 r0 top
RB49 "10M" RESC1508X63N 167.64,250.19 r180 top
RB50 "10M" RESC1508X63N 184.15,250.19 r0 top
RB51 "10M" RESC1508X63N 204.47,250.19 r0 top
RB52 "10M" RESC1508X63N 187.96,250.19 r180 top
RB53 "10M" RESC1508X63N 208.28,250.19 r180 top
RB54 "10M" RESC1508X63N 224.79,250.19 r0 top
RB55 "10M" RESC1508X63N 228.6,250.19 r180 top
RB56 "10M" RESC1508X63N 245.11,250.19 r0 top
RB57 "10M" RESC1508X63N 248.92,250.19 r180 top
RB58 "10M" RESC1508X63N 265.43,250.19 r0 top
RB59 "10M" RESC1508X63N 127,247.65 r180 top
RB60 "10M" RESC1508X63N 143.51,247.65 r0 top
RB61 "10M" RESC1508X63N 147.32,247.65 r180 top
RB62 "10M" RESC1508X63N 163.83,247.65 r0 top
RB63 "10M" RESC1508X63N 167.64,247.65 r180 top
RB64 "10M" RESC1508X63N 184.15,247.65 r0 top
RB65 "10M" RESC1508X63N 204.47,247.65 r0 top
RB66 "10M" RESC1508X63N 187.96,247.65 r180 top
RB67 "10M" RESC1508X63N 208.28,247.65 r180 top
RB68 "10M" RESC1508X63N 224.79,247.65 r0 top
RB69 "10M" RESC1508X63N 228.6,247.65 r180 top
RB70 "10M" RESC1508X63N 245.11,247.65 r0 top
RB71 "10M" RESC1508X63N 248.92,247.65 r180 top
RB72 "10M" RESC1508X63N 265.43,247.65 r0 top
RB73 "10M" RESC1508X63N 106.68,242.57 r180 top
RB74 "10M" RESC1508X63N 123.19,242.57 r0 top
RB75 "10M" RESC1508X63N 143.51,242.57 r0 top
RB76 "10M" RESC1508X63N 147.32,242.57 r180 top
RB77 "10M" RESC1508X63N 167.64,242.57 r180 top
RB78 "10M" RESC1508X63N 184.15,242.57 r0 top
RB79 "10M" RESC1508X63N 204.47,242.57 r0 top
RB80 "10M" RESC1508X63N 127,242.57 r180 top
RB81 "10M" RESC1508X63N 163.83,242.57 r0 top
RB82 "10M" RESC1508X63N 187.96,242.57 r180 top
RB83 "10M" RESC1508X63N 208.28,242.57 r180 top
RB84 "10M" RESC1508X63N 224.79,242.57 r0 top
RB85 "10M" RESC1508X63N 228.6,242.57 r180 top
RB86 "10M" RESC1508X63N 245.11,242.57 r0 top
RB87 "10M" RESC1508X63N 248.92,242.57 r180 top
RB88 "10M" RESC1508X63N 265.43,242.57 r0 top
RB89 "10M" RESC1508X63N 106.68,240.03 r180 top
RB90 "10M" RESC1508X63N 123.19,240.03 r0 top
RB91 "10M" RESC1508X63N 143.51,240.03 r0 top
RB92 "10M" RESC1508X63N 147.32,240.03 r180 top
RB93 "10M" RESC1508X63N 167.64,240.03 r180 top
RB94 "10M" RESC1508X63N 184.15,240.03 r0 top
RB95 "10M" RESC1508X63N 204.47,240.03 r0 top
RB96 "10M" RESC1508X63N 127,240.03 r180 top
RB97 "10M" RESC1508X63N 163.83,240.03 r0 top
RB98 "10M" RESC1508X63N 187.96,240.03 r180 top
RB99 "10M" RESC1508X63N 208.28,240.03 r180 top
RB100 "10M" RESC1508X63N 224.79,240.03 r0 top
RB101 "10M" RESC1508X63N 228.6,240.03 r180 top
RB102 "10M" RESC1508X63N 245.11,240.03 r0 top
RB103 "10M" RESC1508X63N 248.92,240.03 r180 top
RB104 "10M" RESC1508X63N 265.43,240.03 r0 top
RB105 "10M" RESC1508X63N 106.68,237.49 r180 top
RB106 "10M" RESC1508X63N 123.19,237.49 r0 top
RB107 "10M" RESC1508X63N 143.51,237.49 r0 top
RB108 "10M" RESC1508X63N 147.32,237.49 r180 top
RB109 "10M" RESC1508X63N 167.64,237.49 r180 top
RB110 "10M" RESC1508X63N 184.15,237.49 r0 top
RB111 "10M" RESC1508X63N 204.47,237.49 r0 top
RB112 "10M" RESC1508X63N 127,237.49 r180 top
RB113 "10M" RESC1508X63N 163.83,237.49 r0 top
RB114 "10M" RESC1508X63N 187.96,237.49 r180 top
RB115 "10M" RESC1508X63N 208.28,237.49 r180 top
RB116 "10M" RESC1508X63N 224.79,237.49 r0 top
RB117 "10M" RESC1508X63N 228.6,237.49 r180 top
RB118 "10M" RESC1508X63N 245.11,237.49 r0 top
RB119 "10M" RESC1508X63N 248.92,237.49 r180 top
RB120 "10M" RESC1508X63N 265.43,237.49 r0 top
RB121 "10M" RESC1508X63N 106.68,234.95 r180 top
RB122 "10M" RESC1508X63N 143.51,234.95 r0 top
RB123 "10M" RESC1508X63N 147.32,234.95 r180 top
RB124 "10M" RESC1508X63N 167.64,234.95 r180 top
RB125 "10M" RESC1508X63N 184.15,234.95 r0 top
RB126 "10M" RESC1508X63N 204.47,234.95 r0 top
RB127 "10M" RESC1508X63N 127,234.95 r180 top
RB128 "10M" RESC1508X63N 163.83,234.95 r0 top
RB129 "10M" RESC1508X63N 187.96,234.95 r180 top
RB130 "10M" RESC1508X63N 208.28,234.95 r180 top
RB131 "10M" RESC1508X63N 224.79,234.95 r0 top
RB132 "10M" RESC1508X63N 228.6,234.95 r180 top
RB133 "10M" RESC1508X63N 245.125,234.95 r0 top
RB134 "10M" RESC1508X63N 248.92,234.95 r180 top
RB135 "10M" RESC1508X63N 265.43,234.95 r0 top
RS1 "0" RESC1608X55N 171.45,267.97 r0 top
RS2 "0" RESC1608X55N 180.34,267.97 r180 top
RS3 "0" RESC1608X55N 191.77,267.97 r0 top
RS4 "0" RESC1608X55N 200.66,267.97 r180 top
RS5 "0" RESC1608X55N 171.45,265.43 r0 top
RS6 "0" RESC1608X55N 180.34,265.43 r180 top
RS7 "0" RESC1608X55N 191.77,265.43 r0 top
RS8 "0" RESC1608X55N 200.66,265.43 r180 top
RS9 "0" RESC1608X55N 171.45,262.89 r0 top
RS10 "0" RESC1608X55N 180.34,262.89 r180 top
RS11 "0" RESC1608X55N 191.77,262.89 r0 top
RS12 "0" RESC1608X55N 200.66,262.89 r180 top
RS13 "0" RESC1608X55N 171.45,260.35 r0 top
RS14 "0" RESC1608X55N 180.34,260.35 r180 top
RS15 "0" RESC1608X55N 191.77,260.35 r0 top
RS16 "0" RESC1608X55N 200.66,260.35 r180 top
RS17 "0" RESC1608X55N 130.81,255.27 r0 top
RS18 "0" RESC1608X55N 139.7,255.27 r180 top
RS19 "0" RESC1608X55N 151.13,255.27 r0 top
RS20 "0" RESC1608X55N 160.02,255.27 r180 top
RS21 "0" RESC1608X55N 171.45,255.27 r0 top
RS22 "0" RESC1608X55N 180.34,255.27 r180 top
RS23 "0" RESC1608X55N 200.66,255.27 r180 top
RS24 "0" RESC1608X55N 191.77,255.27 r0 top
RS25 "0" RESC1608X55N 212.09,255.27 r0 top
RS26 "0" RESC1608X55N 220.98,255.27 r180 top
RS27 "0" RESC1608X55N 232.41,255.27 r0 top
RS28 "0" RESC1608X55N 241.3,255.27 r180 top
RS29 "0" RESC1608X55N 252.73,255.27 r0 top
RS30 "0" RESC1608X55N 261.62,255.27 r180 top
RS31 "0" RESC1608X55N 130.81,252.73 r0 top
RS32 "0" RESC1608X55N 139.7,252.73 r180 top
RS33 "0" RESC1608X55N 151.13,252.73 r0 top
RS34 "0" RESC1608X55N 160.02,252.73 r180 top
RS35 "0" RESC1608X55N 171.45,252.73 r0 top
RS36 "0" RESC1608X55N 180.34,252.73 r180 top
RS37 "0" RESC1608X55N 200.66,252.73 r180 top
RS38 "0" RESC1608X55N 191.77,252.73 r0 top
RS39 "0" RESC1608X55N 212.09,252.73 r0 top
RS40 "0" RESC1608X55N 220.98,252.73 r180 top
RS41 "0" RESC1608X55N 232.41,252.73 r0 top
RS42 "0" RESC1608X55N 241.3,252.73 r180 top
RS43 "0" RESC1608X55N 252.73,252.73 r0 top
RS44 "0" RESC1608X55N 261.62,252.73 r180 top
RS45 "0" RESC1608X55N 130.81,250.19 r0 top
RS46 "0" RESC1608X55N 139.7,250.19 r180 top
RS47 "0" RESC1608X55N 151.13,250.19 r0 top
RS48 "0" RESC1608X55N 160.02,250.19 r180 top
RS49 "0" RESC1608X55N 171.45,250.19 r0 top
RS50 "0" RESC1608X55N 180.34,250.19 r180 top
RS51 "0" RESC1608X55N 200.66,250.19 r180 top
RS52 "0" RESC1608X55N 191.77,250.19 r0 top
RS53 "0" RESC1608X55N 212.09,250.19 r0 top
RS54 "0" RESC1608X55N 220.98,250.19 r180 top
RS55 "0" RESC1608X55N 232.41,250.19 r0 top
RS56 "0" RESC1608X55N 241.3,250.19 r180 top
RS57 "0" RESC1608X55N 252.73,250.19 r0 top
RS58 "0" RESC1608X55N 261.62,250.19 r180 top
RS59 "0" RESC1608X55N 130.81,247.65 r0 top
RS60 "0" RESC1608X55N 139.7,247.65 r180 top
RS61 "0" RESC1608X55N 151.13,247.65 r0 top
RS62 "0" RESC1608X55N 160.02,247.65 r180 top
RS63 "0" RESC1608X55N 171.45,247.65 r0 top
RS64 "0" RESC1608X55N 180.34,247.65 r180 top
RS65 "0" RESC1608X55N 200.66,247.65 r180 top
RS66 "0" RESC1608X55N 191.77,247.65 r0 top
RS67 "0" RESC1608X55N 212.09,247.65 r0 top
RS68 "0" RESC1608X55N 220.98,247.65 r180 top
RS69 "0" RESC1608X55N 232.41,247.65 r0 top
RS70 "0" RESC1608X55N 241.3,247.65 r180 top
RS71 "0" RESC1608X55N 252.73,247.65 r0 top
RS72 "0" RESC1608X55N 261.62,247.65 r180 top
RS73 "0" RESC1608X55N 110.49,242.57 r0 top
RS74 "0" RESC1608X55N 119.38,242.57 r180 top
RS75 "0" RESC1608X55N 139.7,242.57 r180 top
RS76 "0" RESC1608X55N 151.13,242.57 r0 top
RS77 "0" RESC1608X55N 171.45,242.57 r0 top
RS78 "0" RESC1608X55N 180.34,242.57 r180 top
RS79 "0" RESC1608X55N 200.66,242.57 r180 top
RS80 "0" RESC1608X55N 130.81,242.57 r0 top
RS81 "0" RESC1608X55N 160.02,242.57 r180 top
RS82 "0" RESC1608X55N 191.77,242.57 r0 top
RS83 "0" RESC1608X55N 212.09,242.57 r0 top
RS84 "0" RESC1608X55N 220.98,242.57 r180 top
RS85 "0" RESC1608X55N 232.41,242.57 r0 top
RS86 "0" RESC1608X55N 241.3,242.57 r180 top
RS87 "0" RESC1608X55N 252.73,242.57 r0 top
RS88 "0" RESC1608X55N 261.62,242.57 r180 top
RS89 "0" RESC1608X55N 110.49,240.03 r0 top
RS90 "0" RESC1608X55N 119.38,240.03 r180 top
RS91 "0" RESC1608X55N 139.7,240.03 r180 top
RS92 "0" RESC1608X55N 151.13,240.03 r0 top
RS93 "0" RESC1608X55N 171.45,240.03 r0 top
RS94 "0" RESC1608X55N 180.34,240.03 r180 top
RS95 "0" RESC1608X55N 200.66,240.03 r180 top
RS96 "0" RESC1608X55N 130.81,240.03 r0 top
RS97 "0" RESC1608X55N 160.02,240.03 r180 top
RS98 "0" RESC1608X55N 191.77,240.03 r0 top
RS99 "0" RESC1608X55N 212.09,240.03 r0 top
RS100 "0" RESC1608X55N 220.98,240.03 r180 top
RS101 "0" RESC1608X55N 232.41,240.03 r0 top
RS102 "0" RESC1608X55N 241.3,240.03 r180 top
RS103 "0" RESC1608X55N 252.73,240.03 r0 top
RS104 "0" RESC1608X55N 261.62,240.03 r180 top
RS105 "0" RESC1608X55N 110.49,237.49 r0 top
RS106 "0" RESC1608X55N 119.38,237.49 r180 top
RS107 "0" RESC1608X55N 139.7,237.49 r180 top
RS108 "0" RESC1608X55N 151.13,237.49 r0 top
RS109 "0" RESC1608X55N 171.45,237.49 r0 top
RS110 "0" RESC1608X55N 180.34,237.49 r180 top
RS111 "0" RESC1608X55N 200.66,237.49 r180 top
RS112 "0" RESC1608X55N 130.81,237.49 r0 top
RS113 "0" RESC1608X55N 160.02,237.49 r180 top
RS114 "0" RESC1608X55N 191.77,237.49 r0 top
RS115 "0" RESC1608X55N 212.09,237.49 r0 top
RS116 "0" RESC1608X55N 220.98,237.49 r180 top
RS117 "0" RESC1608X55N 232.41,237.49 r0 top
RS118 "0" RESC1608X55N 241.3,237.49 r180 top
RS119 "0" RESC1608X55N 252.73,237.49 r0 top
RS120 "0" RESC1608X55N 261.62,237.49 r180 top
RS121 "0" RESC1608X55N 110.49,234.95 r0 top
RS122 "0" RESC1608X55N 139.7,234.95 r180 top
RS123 "0" RESC1608X55N 151.13,234.95 r0 top
RS124 "0" RESC1608X55N 171.45,234.95 r0 top
RS125 "0" RESC1608X55N 180.34,234.95 r180 top
RS126 "0" RESC1608X55N 200.66,234.95 r180 top
RS127 "0" RESC1608X55N 130.81,234.95 r0 top
RS128 "0" RESC1608X55N 160.02,234.95 r180 top
RS129 "0" RESC1608X55N 191.77,234.95 r0 top
RS130 "0" RESC1608X55N 212.09,234.95 r0 top
RS131 "0" RESC1608X55N 220.98,234.95 r180 top
RS132 "0" RESC1608X55N 232.41,234.95 r0 top
RS133 "0" RESC1608X55N 241.3,234.95 r180 top
RS134 "0" RESC1608X55N 252.73,234.95 r0 top
RS135 "0" RESC1608X55N 261.62,234.95 r180 top

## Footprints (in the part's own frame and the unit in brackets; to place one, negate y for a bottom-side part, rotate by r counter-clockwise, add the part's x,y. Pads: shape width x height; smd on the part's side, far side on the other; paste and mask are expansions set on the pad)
c150h100 [mm] "Plated Through Hole: Hole Dia.=1mm Pad Dia.=1.5mm"
  round 1.5 hole 1: 1(0,0)
  silkscreen extent -1.1,-1.1 1.1,1.1
CAPC1608X87N [mm] "Chip Capacitor, Body 1.6x0.8mm IPC Medium Density"
  rect 0.95x1 smd: 1(-0.8,0) 2(0.8,0)
  body extent -0.87,-0.47 0.88,0.48, height 0.87
FIDUCIAL_TOP_C100-200 [mm] "Round Fiducial Target, Top Layer, 1.0mm, Top Solder 2.0mm, Keepout =2.0mm"
  round 1 smd paste-0.51 mask+0.5: FTG2(0,0)
  Top Layer keep-out circle w0.1: c0,0 r1
LEMO_EPK.00.250.NTN [mm] "50 Ohm size 00 Coaxial Elbow (90°) socket"
  round 1.6 hole 0.9: 1(0,0)
  rect 2.2x2.2 / inner round 1.6 / far side round 1.6 hole 0.9: 2(-2.54,-2.54) 2(-2.54,2.54) 2(2.54,-2.54) 2(2.54,2.54)
  Top Layer region: 1.44,3.64 3.64,3.64 3.64,-3.64 1.44,-3.64
  silkscreen extent -3.5,-3.5 14,3.5, body extent -3.5,-3.5 14,3.5, height 7
MILL-MAX_0985-1-15-20-71-14-11-0 [mm] "Probe, Spring-Loaded Pin, 2A Continuous, 3A Peak, -55..125°C (Soldered Pin 3.81mm)"
  round 1.15 hole 0.55: 1(0,0)
  body extent -0.54,-0.54 0.55,0.55, height 6.27
"Net Tie" [mil] "SMD Net Tie"
  rect 5x5 smd paste-2.5 mask-2.5: 1(0,0) 2(10,0)
  Top Layer lines w6: 0,0 10,0
RESC1508X63N [mm] "Chip Resistor, EIA 0603, Metric 1608, Body 1.5x0.8mm, IPC Medium Density"
  rect 0.8x1.02 smd: 1(-0.65,0) 2(0.65,0)
  body extent -0.76,-0.42 0.76,0.43, height 0.63
RESC1608X55N [mm] "Chip Resistor, EIA 0603, Metric 1608, Body 1.6x0.8mm, IPC Medium Density"
  rect 0.9x1 smd: 1(-0.8,0) 2(0.8,0)
  body extent -0.87,-0.47 0.88,0.48, height 0.55
SAMTEC_MTLW-106-07-L-D-250 [mm] "12 Contacts - Pitch 2.54mm - Dual Row Through Mount Straight Header (Post Lead = 6.35mm, Tail Lead 3.05mm, Insulator 1.52mm)"
  round 1.7 hole 1: 1(-6.35,-1.27) 2(-6.35,1.27) 3(-3.81,-1.27) 4(-3.81,1.27) 5(-1.27,-1.27) 6(-1.27,1.27) 7(1.27,-1.27) 8(1.27,1.27) 9(3.81,-1.27) 10(3.81,1.27) 11(6.35,-1.27) 12(6.35,1.27)
  silkscreen extent -7.62,-3.29 7.62,2.51, body extent -7.62,-2.51 7.62,2.51, height 7.87
SAMTEC_MTLW-111-07-L-D-250 [mm] "22 Contacts - Pitch 2.54mm - Dual Row Through Mount Straight Header (Post Lead = 6.35mm, Tail Lead 3.05mm, Insulator 1.52mm)"
  round 1.7 hole 1: 1(-12.7,-1.27) 2(-12.7,1.27) 3(-10.16,-1.27) 4(-10.16,1.27) 5(-7.62,-1.27) 6(-7.62,1.27) 7(-5.08,-1.27) 8(-5.08,1.27) 9(-2.54,-1.27) 10(-2.54,1.27) 11(0,-1.27) 12(0,1.27) 13(2.54,-1.27) 14(2.54,1.27) 15(5.08,-1.27) 16(5.08,1.27) 17(7.62,-1.27) 18(7.62,1.27) 19(10.16,-1.27) 20(10.16,1.27) 21(12.7,-1.27) 22(12.7,1.27)
  silkscreen extent -13.97,-3.29 13.97,2.51, body extent -13.97,-2.51 13.97,2.51, height 7.87
SAMTEC_MTLW-116-07-L-D-250 [mm] "32 Contacts - Pitch 2.54mm - Dual Row Through Mount Straight Header (Post Lead = 6.35mm, Tail Lead 3.05mm, Insulator 1.52mm)"
  round 1.7 hole 1: 1(-19.05,-1.27) 2(-19.05,1.27) 3(-16.51,-1.27) 4(-16.51,1.27) 5(-13.97,-1.27) 6(-13.97,1.27) 7(-11.43,-1.27) 8(-11.43,1.27) 9(-8.89,-1.27) 10(-8.89,1.27) 11(-6.35,-1.27) 12(-6.35,1.27) 13(-3.81,-1.27) 14(-3.81,1.27) 15(-1.27,-1.27) 16(-1.27,1.27) 17(1.27,-1.27) 18(1.27,1.27) 19(3.81,-1.27) 20(3.81,1.27) 21(6.35,-1.27) 22(6.35,1.27) 23(8.89,-1.27) 24(8.89,1.27) 25(11.43,-1.27) 26(11.43,1.27) 27(13.97,-1.27) 28(13.97,1.27) 29(16.51,-1.27) 30(16.51,1.27) 31(19.05,-1.27) 32(19.05,1.27)
  silkscreen extent -20.32,-3.29 20.32,2.51, body extent -20.32,-2.51 20.32,2.51, height 7.87
SAMTEC_SSW-104-02-L-S-RA [mm] "4 Contacts, Pitch 2.54mm, Single Row Through Mount Right Angle Socket (Lead Length 2.54mm)"
  rect 1.8x1.8 hole 1.1: 1(3.81,0)
  round 1.8 hole 1.1: 2(1.27,0) 3(-1.27,0) 4(-3.81,0)
  silkscreen extent -5.33,-0.18 5.59,10.03, body extent -5.33,-0.2 5.33,10.03, height 2.41
SENSIRION_SHT2X [mm] "SON, 1.00mm, Pitch; 6 Pin, 3.00mm W X 3.00mm L X 1.20mm H body (W/Thermal Tab 1.40 X 2.3mm), SEMIRION DFN"
  rect 0.6x0.4 smd: 1(1.4,-1) 2(1.4,0) 3(1.4,1) 4(-1.4,1) 5(-1.4,0) 6(-1.4,-1)
  rect 1.5x2.4 smd: 7(0,0)
  silkscreen extent -1.5,-1.55 2.37,1.55, body extent -1.5,-1.5 1.5,1.5, height 1.05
